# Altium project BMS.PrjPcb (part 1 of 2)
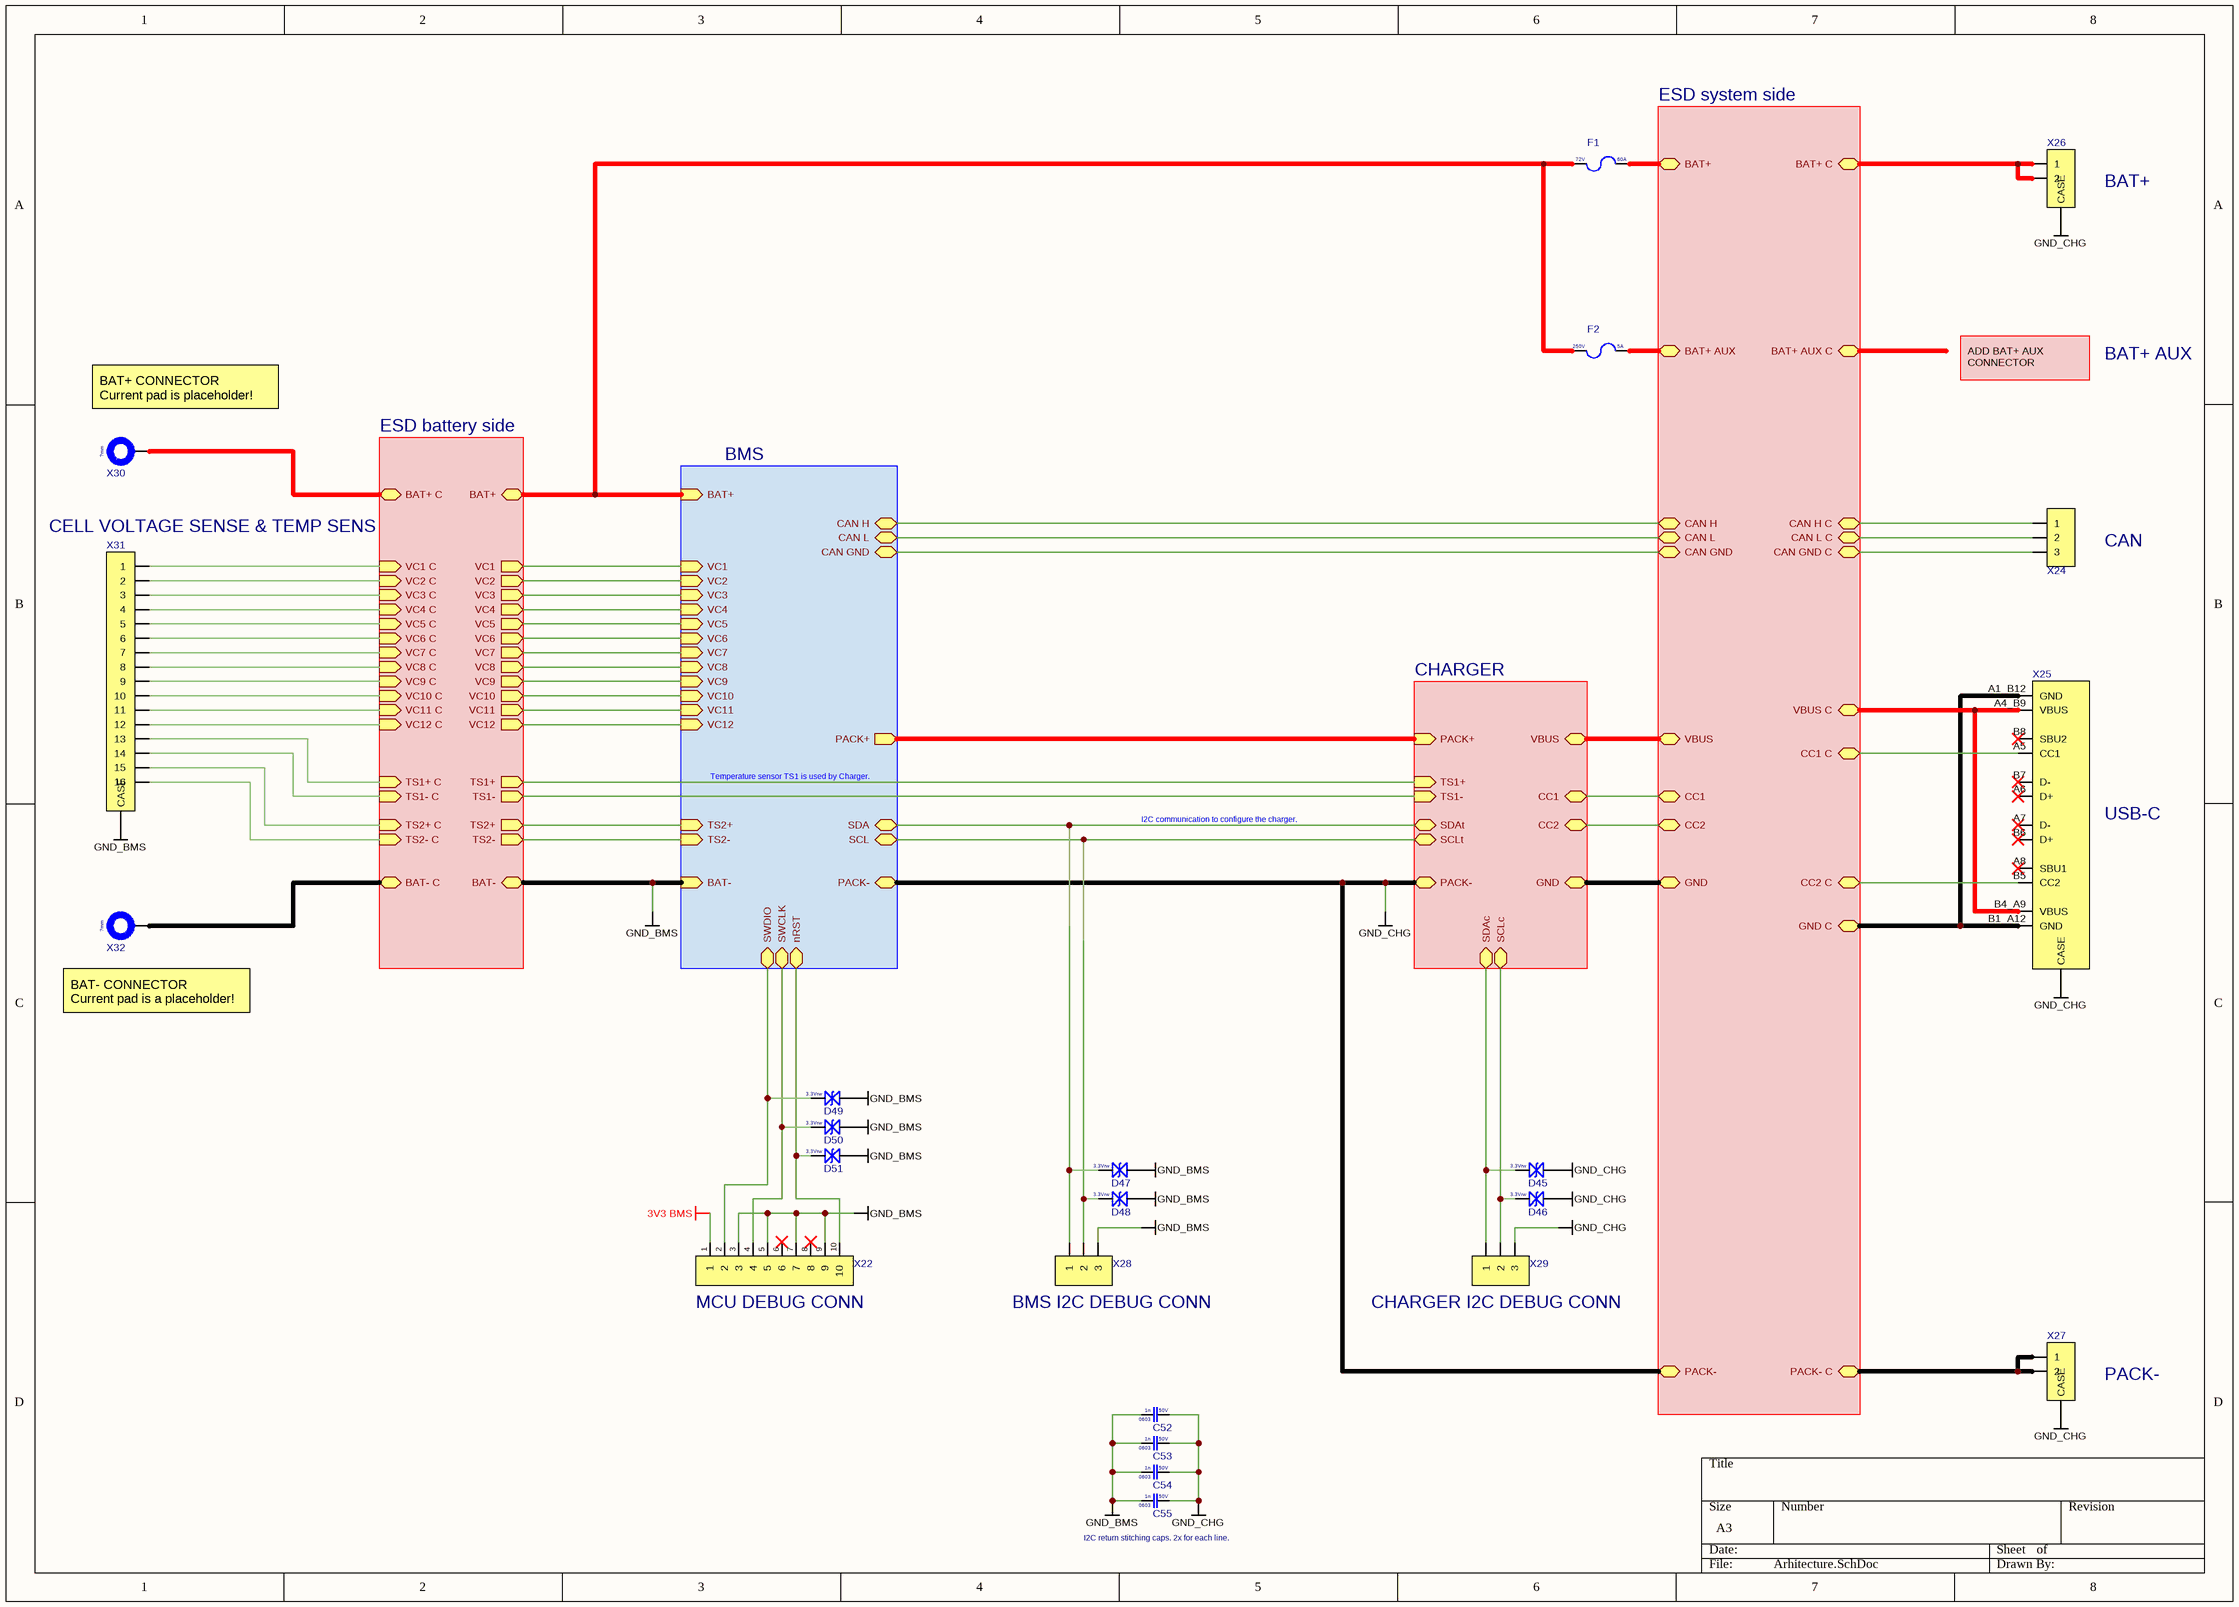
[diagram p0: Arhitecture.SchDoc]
15 sheets, 356 parts. Net scope: hierarchical (ports join the sheet entries above them; power ports are global).
Board file: PCB.PcbDoc
Sheets:
  Arhitecture.SchDoc
    BMS = BMS.SchDoc
      BQ76952 BMS = BQ76952 BMS.SchDoc
      BQ34Z100 FUEL GAUGE = BQ34Z100 FUEL GAUGE.SchDoc
      MCU = MCU.SchDoc
      BAT+ to 5V1 STEP-DOWN = BAT+ to 5V1 STEP-DOWN.SchDoc
      5V to 3V3 LDO = 5V to 3V3 LDO.SchDoc
    CHARGER = CHARGER.SchDoc
      USB PROTECTION = USB protection.SchDoc
      USB PD = USB PD.SchDoc
      POWER PATH SWITCH = Power path switch.SchDoc
      CHARGER BQ25756 = Charger BQ25756.SchDoc
      POWER DISTRIBUTION = Power distribution.SchDoc
    ESD system side = ESD system side.SchDoc
    ESD battery side = ESD battery side.SchDoc

## Sheet Arhitecture.SchDoc
size A3; SheetNumber: 1; SheetTotal: 15

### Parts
C52  Voltage Rating: 50V  Case Code (Imperial): 0603  Capacitance: 1n  [CAP 0603]  (hidden comment: CL10B102KB8NNNC)
C53  Voltage Rating: 50V  Case Code (Imperial): 0603  Capacitance: 1n  [CAP 0603]  (hidden comment: CL10B102KB8NNNC)
C54  Voltage Rating: 50V  Case Code (Imperial): 0603  Capacitance: 1n  [CAP 0603]  (hidden comment: CL10B102KB8NNNC)
C55  Voltage Rating: 50V  Case Code (Imperial): 0603  Capacitance: 1n  [CAP 0603]  (hidden comment: CL10B102KB8NNNC)
D45  V_RWM: 3.3Vrw  [SOD-523]  (hidden comment: H3V3LD5B)
D46  V_RWM: 3.3Vrw  [SOD-523]  (hidden comment: H3V3LD5B)
D47  V_RWM: 3.3Vrw  [SOD-523]  (hidden comment: H3V3LD5B)
D48  V_RWM: 3.3Vrw  [SOD-523]  (hidden comment: H3V3LD5B)
D49  V_RWM: 3.3Vrw  [SOD-523]  (hidden comment: H3V3LD5B)
D50  V_RWM: 3.3Vrw  [SOD-523]  (hidden comment: H3V3LD5B)
D51  V_RWM: 3.3Vrw  [SOD-523]  (hidden comment: H3V3LD5B)
F1  Voltage: 72V  Hold Current: 60A  [TB60]  (hidden comment: TB60)
F2  Voltage: 250V  Hold Current: 5A  [JFC2410-1500TS]  (hidden comment: JFC2410-1500TS)
X22  HX IDC127-2-05-S-4.9  [JTAG Cortex connector]  (value not drawn)
X24  S3B-XH-A-1(LF)(SN)  [S3B-XH-A-1(LF)(SN)]  (value not drawn)
X25  USB-TYPE-C-018  [TYPE-C 16PIN 2MD]  (value not drawn)
X26  XT30PW-M30.G.Y  [XT30PW-M30.G.Y]  (value not drawn)
X27  XT30PW-M30.G.Y  [XT30PW-M30.G.Y]  (value not drawn)
X28  2.54-1*3PPin  [Pin header 1x3 2.54mmP THT Vertical]  (value not drawn)
X29  2.54-1*3PPin  [Pin header 1x3 2.54mmP THT Vertical]  (value not drawn)
X30  Hole Diameter: ?mm  [SolderPad THT 1.9mm AWG14]  (hidden comment: Solder Pad THT)  (no BOM)
X31  FPC-1.0FX-16PWCR-H20  [FPC-1.0FX-16PWCR-H20]  (value not drawn)
X32  Hole Diameter: ?mm  [SolderPad THT 1.9mm AWG14]  (hidden comment: Solder Pad THT)  (no BOM)

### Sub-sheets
BMS = BMS.SchDoc: BAT+ (in), BAT- (in), VC1 (in), VC2 (in), VC3 (in), VC4 (in), VC5 (in), VC6 (in), VC7 (in), VC8 (in), VC9 (in), VC10 (in), VC11 (in), VC12 (in), PACK+ (out), PACK- (bidir), SCL (bidir), SDA (bidir), CAN H (bidir), CAN L (bidir), TS2+ (in), TS2- (in), SWDIO (bidir), SWCLK (bidir), nRST (bidir), CAN GND (bidir)
CHARGER = CHARGER.SchDoc: PACK+ (in), PACK- (bidir), SDAt (bidir), SCLt (bidir), TS1+ (in), TS1- (in), SDAc (bidir), SCLc (bidir), CC1 (bidir), CC2 (bidir), GND (bidir), VBUS (bidir)
ESD battery side = ESD battery side.schDoc: VC1 C (in), VC2 C (in), VC3 C (in), VC4 C (in), VC5 C (in), VC6 C (in), VC7 C (in), VC8 C (in), VC9 C (in), VC10 C (in), VC11 C (in), VC12 C (in), TS1+ C (in), TS1- C (in), TS2+ C (in), TS2- C (in), VC1 (out), VC2 (out), VC3 (out), VC4 (out), VC5 (out), VC6 (out), VC7 (out), VC8 (out), VC9 (out), VC10 (out), VC11 (out), VC12 (out), TS1+ (out), TS1- (out), TS2+ (out), TS2- (out), BAT+ C (bidir), BAT- C (bidir), BAT- (bidir), BAT+ (bidir)
ESD system side = ESD system side.SchDoc: CAN H (bidir), CAN L (bidir), CAN GND (bidir), CAN H C (bidir), CAN L C (bidir), CAN GND C (bidir), VBUS C (bidir), GND C (bidir), CC1 C (bidir), CC2 C (bidir), VBUS (bidir), CC1 (bidir), CC2 (bidir), GND (bidir), BAT+ C (bidir), BAT+ (bidir), PACK- C (bidir), PACK- (bidir), BAT+ AUX (bidir), BAT+ AUX C (bidir)

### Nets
3V3 BMS: X22.1  [project net VDD]
GND CAN: X24.3 ; sheet BMS/CAN GND, sheet ESD system side/CAN GND, sheet ESD system side/CAN GND C
GND_BMS: C52.1 C53.1 C54.1 C55.1 D47.A D48.A D49.A D50.A D51.A X22.3 X22.5 X22.7 X22.9 X28.3 X31.16 X31.CASE X32.1 ; sheet BMS/BAT-, sheet BMS/TS2-, sheet ESD battery side/TS2- C, sheet ESD battery side/TS2-, sheet ESD battery side/BAT- C, sheet ESD battery side/BAT-
GND_CHG: C52.2 C53.2 C54.2 C55.2 D45.A D46.A X25.A1_B12(GND) X25.B1_A12(GND) X25.CASE X26.CASE X27.1 X27.2 X27.CASE X29.3 ; sheet BMS/PACK-, sheet CHARGER/PACK-, sheet CHARGER/GND, sheet ESD system side/GND C, sheet ESD system side/GND, sheet ESD system side/PACK- C, sheet ESD system side/PACK-
BAT+: F1.1 F2.1 X30.1 ; sheet BMS/BAT+, sheet ESD battery side/BAT+ C, sheet ESD battery side/BAT+
C_CC1: X25.A5(CC1) ; sheet CHARGER/CC1, sheet ESD system side/CC1 C, sheet ESD system side/CC1
C_CC2: X25.B5(CC2) ; sheet CHARGER/CC2, sheet ESD system side/CC2 C, sheet ESD system side/CC2
CAN H: X24.1 ; sheet BMS/CAN H, sheet ESD system side/CAN H, sheet ESD system side/CAN H C
CAN L: X24.2 ; sheet BMS/CAN L, sheet ESD system side/CAN L, sheet ESD system side/CAN L C
nRST: D51.K X22.10 ; sheet BMS/nRST
PACK+: sheet BMS/PACK+, sheet CHARGER/PACK+
SCL: D46.K X29.2 ; sheet CHARGER/SCLc
SCLt: D48.K X28.2 ; sheet BMS/SCL, sheet CHARGER/SCLt
SDA: D45.K X29.1 ; sheet CHARGER/SDAc
SDAt: D47.K X28.1 ; sheet BMS/SDA, sheet CHARGER/SDAt
TS: X31.13 ; sheet CHARGER/TS1+, sheet ESD battery side/TS1+ C, sheet ESD battery side/TS1+
VBUS: X25.A4_B9(VBUS) X25.B4_A9(VBUS) ; sheet CHARGER/VBUS, sheet ESD system side/VBUS C, sheet ESD system side/VBUS
NetC75_2: F2.2 ; sheet ESD system side/BAT+ AUX, sheet ESD system side/BAT+ AUX C
NetC83_2: X31.15 ; sheet BMS/TS2+, sheet ESD battery side/TS2+ C, sheet ESD battery side/TS2+
NetC107_2: F1.2 X26.1 X26.2 ; sheet ESD system side/BAT+ C, sheet ESD system side/BAT+
NetD40_A: X31.14 ; sheet CHARGER/TS1-, sheet ESD battery side/TS1- C, sheet ESD battery side/TS1-
NetD49_K: D49.K X22.2 ; sheet BMS/SWDIO
NetD50_K: D50.K X22.4 ; sheet BMS/SWCLK
NetR65_1: X31.12 ; sheet BMS/VC12, sheet ESD battery side/VC12 C, sheet ESD battery side/VC12
NetR66_1: X31.11 ; sheet BMS/VC11, sheet ESD battery side/VC11 C, sheet ESD battery side/VC11
NetR67_1: X31.10 ; sheet BMS/VC10, sheet ESD battery side/VC10 C, sheet ESD battery side/VC10
NetR68_1: X31.9 ; sheet BMS/VC9, sheet ESD battery side/VC9 C, sheet ESD battery side/VC9
NetR69_1: X31.8 ; sheet BMS/VC8, sheet ESD battery side/VC8 C, sheet ESD battery side/VC8
NetR70_1: X31.7 ; sheet BMS/VC7, sheet ESD battery side/VC7 C, sheet ESD battery side/VC7
NetR71_1: X31.6 ; sheet BMS/VC6, sheet ESD battery side/VC6 C, sheet ESD battery side/VC6
NetR72_1: X31.5 ; sheet BMS/VC5, sheet ESD battery side/VC5 C, sheet ESD battery side/VC5
NetR73_1: X31.4 ; sheet BMS/VC4, sheet ESD battery side/VC4 C, sheet ESD battery side/VC4
NetR74_1: X31.3 ; sheet BMS/VC3, sheet ESD battery side/VC3 C, sheet ESD battery side/VC3
NetR75_1: X31.2 ; sheet BMS/VC2, sheet ESD battery side/VC2 C, sheet ESD battery side/VC2
NetR76_1: X31.1 ; sheet BMS/VC1, sheet ESD battery side/VC1 C, sheet ESD battery side/VC1

Not connected (* = marked no-connect by the designer): X22 6* 8*; X25 A6(D+)* A7(D-)* A8(SBU1)* B6(D+)* B7(D-)* B8(SBU2)*

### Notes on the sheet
- (near X26) BAT+
- (near X30) BAT+ CONNECTOR
  Current pad is placeholder!
- ADD BAT+ AUX CONNECTOR
- BAT+ AUX
- (near X31) CELL VOLTAGE SENSE & TEMP SENS
- CAN
- Temperature sensor TS1 is used by Charger.
- I2C communication to configure the charger.
- (near X25) USB-C
- (near X32) BAT- CONNECTOR
  Current pad is a placeholder!
- (near X22) MCU DEBUG CONN
- (near X28) BMS I2C DEBUG CONN
- (near X29) CHARGER I2C DEBUG CONN
- (near X27) PACK-
- (near C55) I2C return stitching caps. 2x for each line.

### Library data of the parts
C52-C55 = CL10B102KB8NNNC: Cap 1nF 50V 0603 X7R; Manufacturer: Samsung
D45-D51 = H3V3LD5B: ESD TVS 3.3Vrw 0.2uA 12.5pF; Manufacturer: hongjiacheng
F1 = TB60: Fuse SMD 60A 72V 10.3x3.2mm; Manufacturer: TLC Electronic
F2 = JFC2410-1500TS: Fuse SMD 250V 5A 2410; Manufacturer: JDT Fuse
X22 = HX IDC127-2-05-S-4.9: JTAG Cortex MCU Debug connector 2x5P 1.27mmP; Manufacturer: hanxia
X24 = S3B-XH-A-1(LF)(SN): JST XH 1x3 2.50mmP THT Right-angle
X25 = USB-TYPE-C-018: USB-C 16P Right-angle; Manufacturer: DEALON
X26 X27 = XT30PW-M30.G.Y: XT30 Male THT Right-angle; Manufacturer: Changzhou Amass Elec
X28 X29 = 2.54-1*3PPin: Pin header 1x3 2.54mmP THT Vertical; Manufacturer: BOOMELE
X31 = FPC-1.0FX-16PWCR-H20: FPC connector 16p 1.0mmP SMD Right-angle; Manufacturer: XUNPU

## Sheet BMS.SchDoc
size A3; SheetNumber: 8; SheetTotal: 15
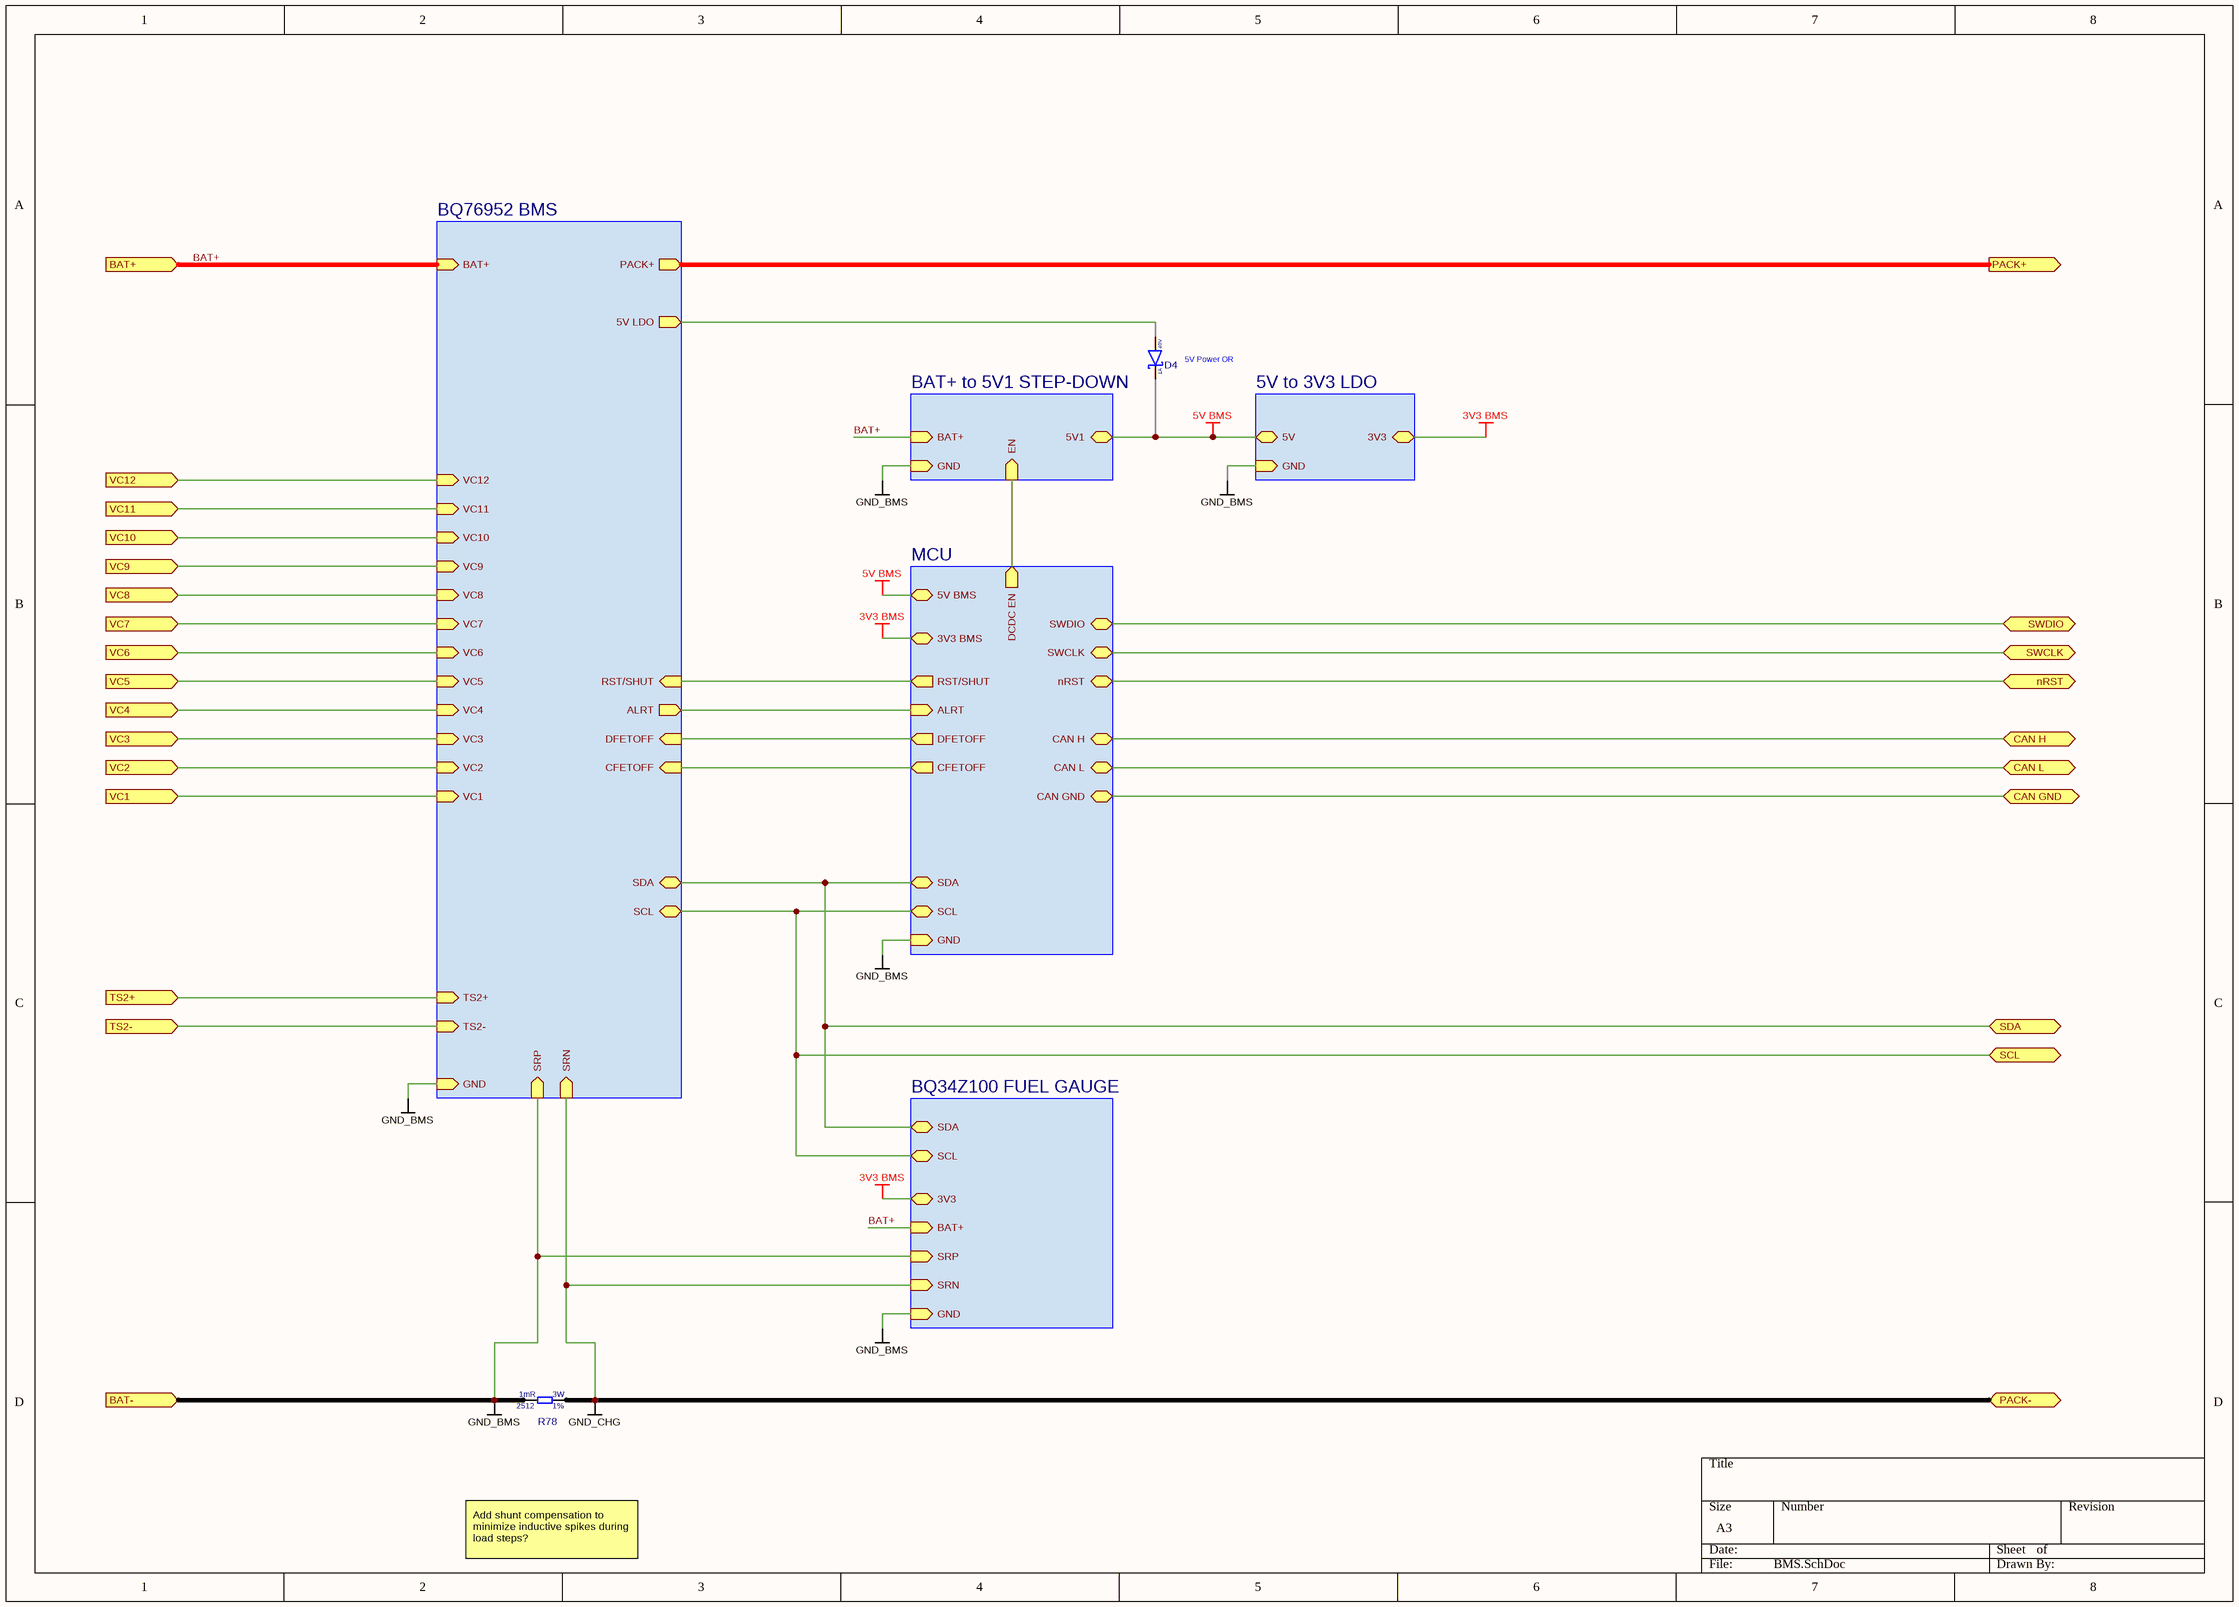
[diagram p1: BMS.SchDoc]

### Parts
D4  Forward Current: 1A  Reverse Voltage: 40V  [SOD-323]  (hidden comment: 1N5819WS)
R78  Resistance Tolerance: 1%  Resistance: 1mR  Power Rating: 3W  Case Code (Imperial): 2512  [2512 Shunt]  (hidden comment: HoYLR2512E-3W-1mR-1%)

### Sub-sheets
5V to 3V3 LDO = 5V to 3V3 LDO.SchDoc: 5V (bidir), 3V3 (bidir), GND (in)
BAT+ to 5V1 STEP-DOWN = BAT+ to 5V1 STEP-DOWN.SchDoc: 5V1 (bidir), BAT+ (in), EN (in), GND (in)
BQ34Z100 FUEL GAUGE = BQ34Z100 FUEL GAUGE.SchDoc: SRP (in), SRN (in), SDA (bidir), SCL (bidir), BAT+ (in), GND (in), 3V3 (bidir)
BQ76952 BMS = BQ76952 BMS.SchDoc: VC12 (in), VC11 (in), VC10 (in), VC9 (in), VC8 (in), VC7 (in), VC6 (in), VC5 (in), VC4 (in), VC3 (in), VC2 (in), VC1 (in), TS2+ (in), TS2- (in), BAT+ (in), PACK+ (out), 5V LDO (out), SRP (in), SRN (in), SDA (bidir), SCL (bidir), ALRT (out), DFETOFF (in), CFETOFF (in), RST/SHUT (in), GND (in)
MCU = MCU.SchDoc: DCDC EN (out), 5V BMS (bidir), 3V3 BMS (bidir), SDA (bidir), SCL (bidir), ALRT (in), DFETOFF (out), CFETOFF (out), RST/SHUT (out), CAN H (bidir), CAN L (bidir), GND (in), nRST (bidir), SWCLK (bidir), SWDIO (bidir), CAN GND (bidir)

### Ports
BAT+ (in, see Arhitecture[3B], BAT+ to 5V1 STEP-DOWN[3B], BQ34Z100 FUEL GAUGE[3A], BQ76952 BMS[1A], ESD battery side[5A]), BAT- (in, see Arhitecture[3C], ESD battery side[5C]), CAN GND (bidir, see Arhitecture[4B], ESD system side[3B], MCU[8B]), CAN H (bidir, see Arhitecture[4B], ESD system side[3B], MCU[8A]), CAN L (bidir, see Arhitecture[4B], ESD system side[3B], MCU[8B]), nRST (bidir, see Arhitecture[3C], MCU[8C]), PACK+ (out, see Arhitecture[4B], BQ76952 BMS[8A], Charger BQ25756[1A], CHARGER[1B], Power distribution[3A]), PACK- (bidir, see Arhitecture[4C], CHARGER[1C], ESD system side[3C]), SCL (bidir, see Arhitecture[4C], BQ34Z100 FUEL GAUGE[5B], BQ76952 BMS[7C], MCU[1B]), SDA (bidir, see Arhitecture[4C], BQ34Z100 FUEL GAUGE[5B], BQ76952 BMS[7C], MCU[1B]), SWCLK (bidir, see Arhitecture[3C], MCU[8C]), SWDIO (bidir, see Arhitecture[3C], MCU[8C]), TS2+ (in, see Arhitecture[3C], BQ76952 BMS[3C], ESD battery side[5C]), TS2- (in, see Arhitecture[3C], BQ76952 BMS[3C], ESD battery side[5C]), VC1 (in, see Arhitecture[3B], BQ76952 BMS[1C], ESD battery side[5B]), VC2 (in, see Arhitecture[3B], BQ76952 BMS[1C], ESD battery side[5B]), VC3 (in, see Arhitecture[3B], BQ76952 BMS[1C], ESD battery side[5B]), VC4 (in, see Arhitecture[3B], BQ76952 BMS[1C], ESD battery side[5B]), VC5 (in, see Arhitecture[3B], BQ76952 BMS[1C], ESD battery side[5B]), VC6 (in, see Arhitecture[3B], BQ76952 BMS[1C], ESD battery side[5B]), VC7 (in, see Arhitecture[3B], BQ76952 BMS[1C], ESD battery side[5B]), VC8 (in, see Arhitecture[3B], BQ76952 BMS[1B], ESD battery side[5B]), VC9 (in, see Arhitecture[3B], BQ76952 BMS[1B], ESD battery side[5B]), VC10 (in, see Arhitecture[3B], BQ76952 BMS[1B], ESD battery side[5B]), VC11 (in, see Arhitecture[3B], BQ76952 BMS[1B], ESD battery side[5B]), VC12 (in, see Arhitecture[3B], BQ76952 BMS[1B], ESD battery side[5B])

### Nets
3V3 BMS: sheet BQ34Z100 FUEL GAUGE/3V3, sheet MCU/3V3 BMS, sheet 5V to 3V3 LDO/3V3  [project net VDD]
5V BMS: D4.K ; sheet MCU/5V BMS, sheet BAT+ to 5V1 STEP-DOWN/5V1, sheet 5V to 3V3 LDO/5V
GND CAN: port CAN GND, sheet MCU/CAN GND
GND_BMS: R78.1 ; port BAT-, port TS2-, sheet BQ76952 BMS/TS2-, sheet BQ76952 BMS/SRP, sheet BQ76952 BMS/GND, sheet BQ34Z100 FUEL GAUGE/SRP, sheet BQ34Z100 FUEL GAUGE/GND, sheet MCU/GND, sheet BAT+ to 5V1 STEP-DOWN/GND, sheet 5V to 3V3 LDO/GND
GND_CHG: R78.2 ; port PACK-, sheet BQ76952 BMS/SRN, sheet BQ34Z100 FUEL GAUGE/SRN
BAT+: port BAT+, sheet BQ76952 BMS/BAT+, sheet BQ34Z100 FUEL GAUGE/BAT+, sheet BAT+ to 5V1 STEP-DOWN/BAT+
CAN H: port CAN H, sheet MCU/CAN H
CAN L: port CAN L, sheet MCU/CAN L
nRST: port nRST, sheet MCU/nRST
PACK+: port PACK+, sheet BQ76952 BMS/PACK+
REG1: D4.A ; sheet BQ76952 BMS/5V LDO
SCLt: port SCL, sheet BQ76952 BMS/SCL, sheet BQ34Z100 FUEL GAUGE/SCL, sheet MCU/SCL
SDAt: port SDA, sheet BQ76952 BMS/SDA, sheet BQ34Z100 FUEL GAUGE/SDA, sheet MCU/SDA
NetC83_2: port TS2+, sheet BQ76952 BMS/TS2+
NetD49_K: port SWDIO, sheet MCU/SWDIO
NetD50_K: port SWCLK, sheet MCU/SWCLK
NetIC9_29: sheet BQ76952 BMS/CFETOFF, sheet MCU/CFETOFF
NetIC9_30: sheet BQ76952 BMS/DFETOFF, sheet MCU/DFETOFF
NetIC10_16: sheet BQ76952 BMS/ALRT, sheet MCU/ALRT
NetIC10_17: sheet BQ76952 BMS/RST/SHUT, sheet MCU/RST/SHUT
NetIC13_3: sheet MCU/DCDC EN, sheet BAT+ to 5V1 STEP-DOWN/EN
NetR65_1: port VC12, sheet BQ76952 BMS/VC12
NetR66_1: port VC11, sheet BQ76952 BMS/VC11
NetR67_1: port VC10, sheet BQ76952 BMS/VC10
NetR68_1: port VC9, sheet BQ76952 BMS/VC9
NetR69_1: port VC8, sheet BQ76952 BMS/VC8
NetR70_1: port VC7, sheet BQ76952 BMS/VC7
NetR71_1: port VC6, sheet BQ76952 BMS/VC6
NetR72_1: port VC5, sheet BQ76952 BMS/VC5
NetR73_1: port VC4, sheet BQ76952 BMS/VC4
NetR74_1: port VC3, sheet BQ76952 BMS/VC3
NetR75_1: port VC2, sheet BQ76952 BMS/VC2
NetR76_1: port VC1, sheet BQ76952 BMS/VC1

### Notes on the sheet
- (near D4) 5V Power OR
- Add shunt compensation to minimize inductive spikes during load steps?

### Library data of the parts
D4 = 1N5819WS: Schottky 40V 1A 600mVf SOD-323; Manufacturer: Guangdong Hottech
R78 = HoYLR2512E-3W-1mR-1%: RES 1mR 2512 3W 1%; Manufacturer: Miliohm

## Sheet BQ76952 BMS.SchDoc
size A3; SheetNumber: 9; SheetTotal: 15
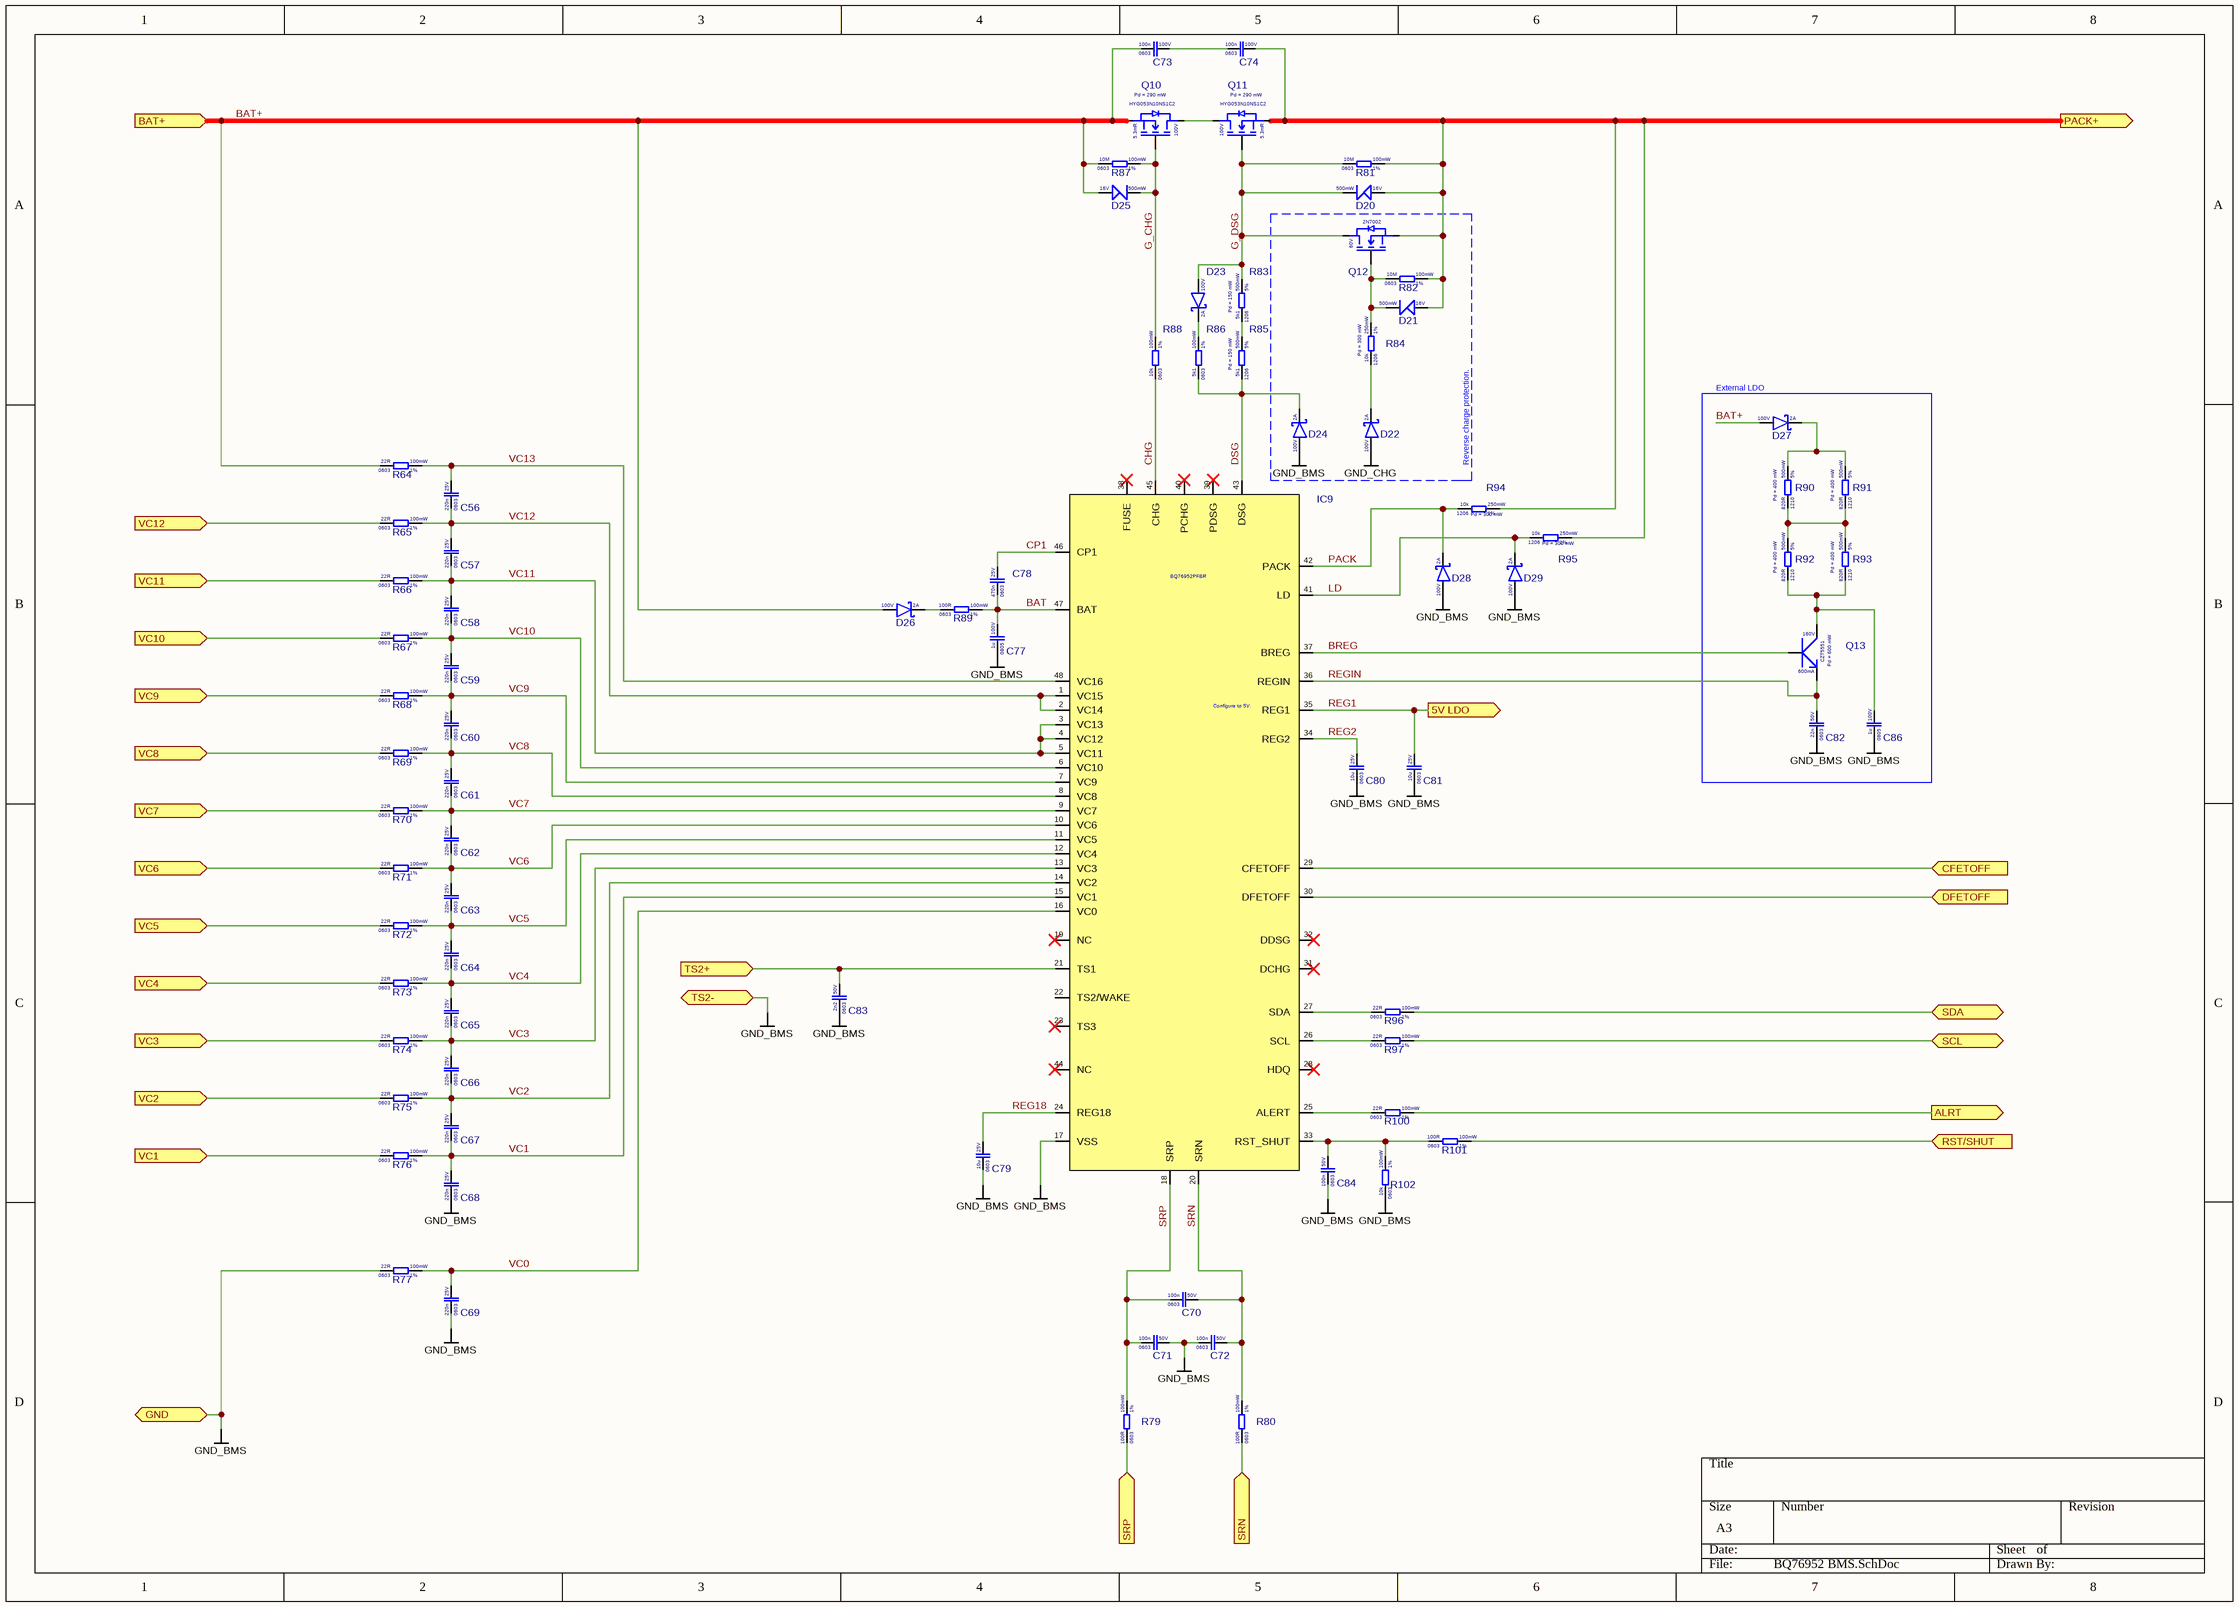
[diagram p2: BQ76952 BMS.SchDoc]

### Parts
C56  Voltage Rating: 25V  Case Code (Imperial): 0603  Capacitance: 220n  [CAP 0603]  (hidden comment: CL10B224KA8NNNC)
C57  Voltage Rating: 25V  Case Code (Imperial): 0603  Capacitance: 220n  [CAP 0603]  (hidden comment: CL10B224KA8NNNC)
C58  Voltage Rating: 25V  Case Code (Imperial): 0603  Capacitance: 220n  [CAP 0603]  (hidden comment: CL10B224KA8NNNC)
C59  Voltage Rating: 25V  Case Code (Imperial): 0603  Capacitance: 220n  [CAP 0603]  (hidden comment: CL10B224KA8NNNC)
C60  Voltage Rating: 25V  Case Code (Imperial): 0603  Capacitance: 220n  [CAP 0603]  (hidden comment: CL10B224KA8NNNC)
C61  Voltage Rating: 25V  Case Code (Imperial): 0603  Capacitance: 220n  [CAP 0603]  (hidden comment: CL10B224KA8NNNC)
C62  Voltage Rating: 25V  Case Code (Imperial): 0603  Capacitance: 220n  [CAP 0603]  (hidden comment: CL10B224KA8NNNC)
C63  Voltage Rating: 25V  Case Code (Imperial): 0603  Capacitance: 220n  [CAP 0603]  (hidden comment: CL10B224KA8NNNC)
C64  Voltage Rating: 25V  Case Code (Imperial): 0603  Capacitance: 220n  [CAP 0603]  (hidden comment: CL10B224KA8NNNC)
C65  Voltage Rating: 25V  Case Code (Imperial): 0603  Capacitance: 220n  [CAP 0603]  (hidden comment: CL10B224KA8NNNC)
C66  Voltage Rating: 25V  Case Code (Imperial): 0603  Capacitance: 220n  [CAP 0603]  (hidden comment: CL10B224KA8NNNC)
C67  Voltage Rating: 25V  Case Code (Imperial): 0603  Capacitance: 220n  [CAP 0603]  (hidden comment: CL10B224KA8NNNC)
C68  Voltage Rating: 25V  Case Code (Imperial): 0603  Capacitance: 220n  [CAP 0603]  (hidden comment: CL10B224KA8NNNC)
C69  Voltage Rating: 25V  Case Code (Imperial): 0603  Capacitance: 220n  [CAP 0603]  (hidden comment: CL10B224KA8NNNC)
C70  Voltage Rating: 50V  Case Code (Imperial): 0603  Capacitance: 100n  [CAP 0603]  (hidden comment: CC0603KRX7R9BB104)
C71  Voltage Rating: 50V  Case Code (Imperial): 0603  Capacitance: 100n  [CAP 0603]  (hidden comment: CC0603KRX7R9BB104)
C72  Voltage Rating: 50V  Case Code (Imperial): 0603  Capacitance: 100n  [CAP 0603]  (hidden comment: CC0603KRX7R9BB104)
C73  Voltage Rating: 100V  Case Code (Imperial): 0603  Capacitance: 100n  [CAP 0603]  (hidden comment: CC0603KRX7R0BB104)
C74  Voltage Rating: 100V  Case Code (Imperial): 0603  Capacitance: 100n  [CAP 0603]  (hidden comment: CC0603KRX7R0BB104)
C77  Voltage Rating: 100V  Case Code (Imperial): 0805  Capacitance: 1u  [Cap_0805]  (hidden comment: CC0805KKX7R0BB105)
C78  Voltage Rating: 25V  Case Code (Imperial): 0603  Capacitance: 470n  [CAP 0603]  (hidden comment: CL10B474KA8NNNC)
C79  Voltage Rating: 25V  Case Code (Imperial): 0603  Capacitance: 10u  [CAP 0603]  (hidden comment: CL10A106MA8NRNC)
C80  Voltage Rating: 25V  Case Code (Imperial): 0603  Capacitance: 10u  [CAP 0603]  (hidden comment: CL10A106MA8NRNC)
C81  Voltage Rating: 25V  Case Code (Imperial): 0603  Capacitance: 10u  [CAP 0603]  (hidden comment: CL10A106MA8NRNC)
C82  Voltage Rating: 50V  Case Code (Imperial): 0603  Capacitance: 22n  [CAP 0603]  (hidden comment: CL10B223KB8NNNC)
C83  Voltage Rating: 50V  Case Code (Imperial): 0603  Capacitance: 2n2  [CAP 0603]  (hidden comment: 0603B222K500NT)
C84  Voltage Rating: 50V  Case Code (Imperial): 0603  Capacitance: 100n  [CAP 0603]  (hidden comment: CC0603KRX7R9BB104)
C86  Voltage Rating: 100V  Case Code (Imperial): 0805  Capacitance: 1u  [Cap_0805]  (hidden comment: CC0805KKX7R0BB105)
D20  Power Rating: 500mW  Reverse Voltage: 16V  [SOD-123]  (hidden comment: BZT52C16)
D21  Power Rating: 500mW  Reverse Voltage: 16V  [SOD-123]  (hidden comment: BZT52C16)
D22  Forward Current: 2A  Reverse Voltage: 100V  [SMAF]  (hidden comment: SS210F)
D23  Forward Current: 2A  Reverse Voltage: 100V  [SMAF]  (hidden comment: SS210F)
D24  Forward Current: 2A  Reverse Voltage: 100V  [SMAF]  (hidden comment: SS210F)
D25  Power Rating: 500mW  Reverse Voltage: 16V  [SOD-123]  (hidden comment: BZT52C16)
D26  Forward Current: 2A  Reverse Voltage: 100V  [SMAF]  (hidden comment: SS210F)
D27  Forward Current: 2A  Reverse Voltage: 100V  [SMAF]  (hidden comment: SS210F)
D28  Forward Current: 2A  Reverse Voltage: 100V  [SMAF]  (hidden comment: SS210F)
D29  Forward Current: 2A  Reverse Voltage: 100V  [SMAF]  (hidden comment: SS210F)
IC9  BQ76952PFBR  [TQFP-48 PFB]
Q10  Pd = 290 mW  Rds: 5.3mR  Voltage: 100V  [PDFN5*6-8L]
Q11  Pd = 290 mW  Rds: 5.3mR  Voltage: 100V  [PDFN5*6-8L]
Q12  Voltage: 60V  [SOT-23 GSD]  (hidden comment: 2N7002)
Q13  Pd = 600 mW  Current: 600mA  Voltage: 160V  [SOT-223 NPN]
R64  Resistance Tolerance: 1%  Resistance: 22R  Power Rating: 100mW  Case Code (Imperial): 0603  [RES_0603]  (hidden comment: 0603WAF220JT5E)
R65  Resistance Tolerance: 1%  Resistance: 22R  Power Rating: 100mW  Case Code (Imperial): 0603  [RES_0603]  (hidden comment: 0603WAF220JT5E)
R66  Resistance Tolerance: 1%  Resistance: 22R  Power Rating: 100mW  Case Code (Imperial): 0603  [RES_0603]  (hidden comment: 0603WAF220JT5E)
R67  Resistance Tolerance: 1%  Resistance: 22R  Power Rating: 100mW  Case Code (Imperial): 0603  [RES_0603]  (hidden comment: 0603WAF220JT5E)
R68  Resistance Tolerance: 1%  Resistance: 22R  Power Rating: 100mW  Case Code (Imperial): 0603  [RES_0603]  (hidden comment: 0603WAF220JT5E)
R69  Resistance Tolerance: 1%  Resistance: 22R  Power Rating: 100mW  Case Code (Imperial): 0603  [RES_0603]  (hidden comment: 0603WAF220JT5E)
R70  Resistance Tolerance: 1%  Resistance: 22R  Power Rating: 100mW  Case Code (Imperial): 0603  [RES_0603]  (hidden comment: 0603WAF220JT5E)
R71  Resistance Tolerance: 1%  Resistance: 22R  Power Rating: 100mW  Case Code (Imperial): 0603  [RES_0603]  (hidden comment: 0603WAF220JT5E)
R72  Resistance Tolerance: 1%  Resistance: 22R  Power Rating: 100mW  Case Code (Imperial): 0603  [RES_0603]  (hidden comment: 0603WAF220JT5E)
R73  Resistance Tolerance: 1%  Resistance: 22R  Power Rating: 100mW  Case Code (Imperial): 0603  [RES_0603]  (hidden comment: 0603WAF220JT5E)
R74  Resistance Tolerance: 1%  Resistance: 22R  Power Rating: 100mW  Case Code (Imperial): 0603  [RES_0603]  (hidden comment: 0603WAF220JT5E)
R75  Resistance Tolerance: 1%  Resistance: 22R  Power Rating: 100mW  Case Code (Imperial): 0603  [RES_0603]  (hidden comment: 0603WAF220JT5E)
R76  Resistance Tolerance: 1%  Resistance: 22R  Power Rating: 100mW  Case Code (Imperial): 0603  [RES_0603]  (hidden comment: 0603WAF220JT5E)
R77  Resistance Tolerance: 1%  Resistance: 22R  Power Rating: 100mW  Case Code (Imperial): 0603  [RES_0603]  (hidden comment: 0603WAF220JT5E)
R79  Resistance Tolerance: 1%  Resistance: 100R  Power Rating: 100mW  Case Code (Imperial): 0603  [RES_0603]  (hidden comment: 0603WAF1000T5E)
R80  Resistance Tolerance: 1%  Resistance: 100R  Power Rating: 100mW  Case Code (Imperial): 0603  [RES_0603]  (hidden comment: 0603WAF1000T5E)
R81  Resistance Tolerance: 1%  Resistance: 10M  Power Rating: 100mW  Case Code (Imperial): 0603  [RES_0603]  (hidden comment: 0603WAF1005T5E)
R82  Resistance Tolerance: 1%  Resistance: 10M  Power Rating: 100mW  Case Code (Imperial): 0603  [RES_0603]  (hidden comment: 0603WAF1005T5E)
R83  Pd = 150 mW  Resistance Tolerance: 5%  Resistance: 5k1  Power Rating: 500mW  Case Code (Imperial): 1206  [RES_1206]
R84  Pd = 300 mW  Resistance Tolerance: 1%  Resistance: 10k  Power Rating: 250mW  Case Code (Imperial): 1206  [RES_1206]
R85  Pd = 150 mW  Resistance Tolerance: 5%  Resistance: 5k1  Power Rating: 500mW  Case Code (Imperial): 1206  [RES_1206]
R86  Resistance Tolerance: 1%  Resistance: 5k1  Power Rating: 100mW  Case Code (Imperial): 0603  [RES_0603]  (hidden comment: 0603WAF5101T5E)
R87  Resistance Tolerance: 1%  Resistance: 10M  Power Rating: 100mW  Case Code (Imperial): 0603  [RES_0603]  (hidden comment: 0603WAF1005T5E)
R88  Resistance Tolerance: 1%  Resistance: 10k  Power Rating: 100mW  Case Code (Imperial): 0603  [RES_0603]  (hidden comment: 0603WAF1002T5E)
R89  Resistance Tolerance: 1%  Resistance: 100R  Power Rating: 100mW  Case Code (Imperial): 0603  [RES_0603]  (hidden comment: 0603WAF1000T5E)
R90  Pd = 400 mW  Resistance Tolerance: 5%  Resistance: 820R  Power Rating: 500mW  Case Code (Imperial): 1210  [RES_1210]
R91  Pd = 400 mW  Resistance Tolerance: 5%  Resistance: 820R  Power Rating: 500mW  Case Code (Imperial): 1210  [RES_1210]
R92  Pd = 400 mW  Resistance Tolerance: 5%  Resistance: 820R  Power Rating: 500mW  Case Code (Imperial): 1210  [RES_1210]
R93  Pd = 400 mW  Resistance Tolerance: 5%  Resistance: 820R  Power Rating: 500mW  Case Code (Imperial): 1210  [RES_1210]
R94  Pd = 300 mW  Resistance Tolerance: 1%  Resistance: 10k  Power Rating: 250mW  Case Code (Imperial): 1206  [RES_1206]
R95  Pd = 300 mW  Resistance Tolerance: 1%  Resistance: 10k  Power Rating: 250mW  Case Code (Imperial): 1206  [RES_1206]
R96  Resistance Tolerance: 1%  Resistance: 22R  Power Rating: 100mW  Case Code (Imperial): 0603  [RES_0603]  (hidden comment: 0603WAF220JT5E)
R97  Resistance Tolerance: 1%  Resistance: 22R  Power Rating: 100mW  Case Code (Imperial): 0603  [RES_0603]  (hidden comment: 0603WAF220JT5E)
R100  Resistance Tolerance: 1%  Resistance: 22R  Power Rating: 100mW  Case Code (Imperial): 0603  [RES_0603]  (hidden comment: 0603WAF220JT5E)
R101  Resistance Tolerance: 1%  Resistance: 100R  Power Rating: 100mW  Case Code (Imperial): 0603  [RES_0603]  (hidden comment: 0603WAF1000T5E)
R102  Resistance Tolerance: 1%  Resistance: 10k  Power Rating: 100mW  Case Code (Imperial): 0603  [RES_0603]  (hidden comment: 0603WAF1002T5E)

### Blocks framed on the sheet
External LDO: C82 C86 D27 Q13 R90-R93

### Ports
5V LDO (out, see BMS[3A]), ALRT (out, see BMS[3B], MCU[1C]), BAT+ (in, see BMS[2A], BAT+ to 5V1 STEP-DOWN[3B], BMS[1A], BQ34Z100 FUEL GAUGE[3A], ESD battery side[5A]), CFETOFF (in, see BMS[3B], MCU[1C]), DFETOFF (in, see BMS[3B], MCU[1C]), GND (bidir, see BMS[2C], 5V to 3V3 LDO[3B], BAT+ to 5V1 STEP-DOWN[3C], BQ34Z100 FUEL GAUGE[3C], MCU[1C]), PACK+ (out, see BMS[3A], BMS[8A], Charger BQ25756[1A], CHARGER[1B], Power distribution[3A]), RST/SHUT (in, see BMS[3B], MCU[1C]), SCL (bidir, see BMS[3C], BMS[8C], BQ34Z100 FUEL GAUGE[5B], MCU[1B]), SDA (bidir, see BMS[3C], BMS[8C], BQ34Z100 FUEL GAUGE[5B], MCU[1B]), SRN (in, see BMS[3C], BQ34Z100 FUEL GAUGE[4C]), SRP (in, see BMS[2C], BQ34Z100 FUEL GAUGE[4C]), TS2+ (in, see BMS[2C], BMS[1C], ESD battery side[5C]), TS2- (bidir, see BMS[2C], BMS[1C], ESD battery side[5C]), VC1 (in, see BMS[2B], BMS[1B], ESD battery side[5B]), VC2 (in, see BMS[2B], BMS[1B], ESD battery side[5B]), VC3 (in, see BMS[2B], BMS[1B], ESD battery side[5B]), VC4 (in, see BMS[2B], BMS[1B], ESD battery side[5B]), VC5 (in, see BMS[2B], BMS[1B], ESD battery side[5B]), VC6 (in, see BMS[2B], BMS[1B], ESD battery side[5B]), VC7 (in, see BMS[2B], BMS[1B], ESD battery side[5B]), VC8 (in, see BMS[2B], BMS[1B], ESD battery side[5B]), VC9 (in, see BMS[2B], BMS[1B], ESD battery side[5B]), VC10 (in, see BMS[2B], BMS[1B], ESD battery side[5B]), VC11 (in, see BMS[2B], BMS[1B], ESD battery side[5B]), VC12 (in, see BMS[2B], BMS[1B], ESD battery side[5B])

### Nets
GND_BMS: C68.1 C69.1 C71.2 C72.1 C77.1 C79.1 C80.1 C81.1 C82.1 C83.1 C84.1 C86.1 D24.A D28.A D29.A IC9.17(VSS) R77.1 R79.1 R102.1 ; port TS2-, port SRP, port GND
GND_CHG: D22.A R80.1 ; port SRN
BAT: C77.2 C78.1 IC9.47(BAT) R89.2
BAT+: C73.1 D25.A D26.A D27.A Q10.S R64.1 R87.1 ; port BAT+
BREG: IC9.37(BREG) Q13.B
CHG: IC9.45(CHG) R88.1
CP1: C78.2 IC9.46(CP1)
DSG: D24.K IC9.43(DSG) R85.1 R86.1
G_CHG: D25.K Q10.G R87.2 R88.2
G_DSG: D20.K D23.A Q11.G Q12.D R81.1 R83.2
LD: D29.K IC9.41(LD) R95.1
PACK: D28.K IC9.42(PACK) R94.1
PACK+: C74.2 D20.A D21.A Q11.S Q12.S R81.2 R82.2 R94.2 R95.2 ; port PACK+
REG1: C81.2 IC9.35(REG1) ; port 5V LDO
REG2: C80.2 IC9.34(REG2)
REG18: C79.2 IC9.24(REG18)
REGIN: C82.2 IC9.36(REGIN) Q13.E
SCLt: R97.2 ; port SCL
SDAt: R96.2 ; port SDA
SRN: C70.2 C72.2 IC9.20(SRN) R80.2
SRP: C70.1 C71.1 IC9.18(SRP) R79.2
VC0: C69.2 IC9.16(VC0) R77.2
VC1: C67.1 C68.2 IC9.15(VC1) R76.2
VC2: C66.1 C67.2 IC9.14(VC2) R75.2
VC3: C65.1 C66.2 IC9.13(VC3) R74.2
VC4: C64.1 C65.2 IC9.12(VC4) R73.2
VC5: C63.1 C64.2 IC9.11(VC5) R72.2
VC6: C62.1 C63.2 IC9.10(VC6) R71.2
VC7: C61.1 C62.2 IC9.9(VC7) R70.2
VC8: C60.1 C61.2 IC9.8(VC8) R69.2
VC9: C59.1 C60.2 IC9.7(VC9) R68.2
VC10: C58.1 C59.2 IC9.6(VC10) R67.2
VC11: C57.1 C58.2 IC9.3(VC13) IC9.4(VC12) IC9.5(VC11) R66.2
VC12: C56.1 C57.2 IC9.1(VC15) IC9.2(VC14) R65.2
VC13: C56.2 IC9.48(VC16) R64.2
NetC73_2: C73.2 C74.1
NetC83_2: C83.2 IC9.21(TS1) ; port TS2+
NetC84_2: C84.2 IC9.33(RST_SHUT) R101.1 R102.2
NetC86_2: C86.2 Q13.C R92.1 R93.1
NetD21_K: D21.K Q12.G R82.1 R84.2
NetD22_K: D22.K R84.1
NetD23_K: D23.K R86.2
NetD26_K: D26.K R89.1
NetD27_K: D27.K R90.2 R91.2
NetIC9_25: IC9.25(ALERT) R100.1
NetIC9_26: IC9.26(SCL) R97.1
NetIC9_27: IC9.27(SDA) R96.1
NetIC9_29: IC9.29(CFETOFF) ; port CFETOFF
NetIC9_30: IC9.30(DFETOFF) ; port DFETOFF
NetIC10_16: R100.2 ; port ALRT
NetIC10_17: R101.2 ; port RST/SHUT
NetQ10_D: Q10.D Q11.D
NetR65_1: R65.1 ; port VC12
NetR66_1: R66.1 ; port VC11
NetR67_1: R67.1 ; port VC10
NetR68_1: R68.1 ; port VC9
NetR69_1: R69.1 ; port VC8
NetR70_1: R70.1 ; port VC7
NetR71_1: R71.1 ; port VC6
NetR72_1: R72.1 ; port VC5
NetR73_1: R73.1 ; port VC4
NetR74_1: R74.1 ; port VC3
NetR75_1: R75.1 ; port VC2
NetR76_1: R76.1 ; port VC1
NetR83_1: R83.1 R85.2
NetR90_1: R90.1 R91.1 R92.2 R93.2

Not connected (* = marked no-connect by the designer): IC9 19(NC)* 22(TS2/WAKE) 23(TS3)* 28(HDQ)* 31(DCHG)* 32(DDSG)* 38(FUSE)* 39(PDSG)* 40(PCHG)* 44(NC)*

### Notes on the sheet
- (near R94) Reverse charge protection.
- (near IC9) Configure to 5V.

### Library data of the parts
C56-C69 = CL10B224KA8NNNC: Cap 220nF 25V 0603 X7R; Manufacturer: Samsung
C70-C72 C84 = CC0603KRX7R9BB104: Cap 100nF 50V 0603 X7R; Manufacturer: Yageo
C73 C74 = CC0603KRX7R0BB104: Cap 100nF 100V 0603 X7R; Manufacturer: YAGEO
C77 C86 = CC0805KKX7R0BB105: Cap 1uF 100V 0805 X7R; Manufacturer: Yageo
C78 = CL10B474KA8NNNC: Cap 470nF 25V 0603 X7R; Manufacturer: Samsung
C79-C81 = CL10A106MA8NRNC: Cap 10uF 25V 0603 X5R; Manufacturer: Samsung
C82 = CL10B223KB8NNNC: Cap 22nF 50V 0603 X7R; Manufacturer: Samsung
C83 = 0603B222K500NT: Cap 2n2F 50V 0603 X7R; Manufacturer: FH
D20 D21 D25 = BZT52C16: Zener 16V 500mW SOD-123; Manufacturer: TWGMC
D22-D24 D26-D29 = SS210F: Schottky 100V 2A 850mVf SMAF; Manufacturer: GOODWORK
IC9 = BQ76952PFBR: BMS IC 3~16s; Manufacturer: Texas Instruments
Q10 Q11 = HYG053N10NS1C2: Nmos 100V 95A 5.3mR PDFN5x6-8L; Manufacturer: HUAYI
Q12 = 2N7002: nMOS 60V 115mA SOT-23; Manufacturer: Jiangsu Changjing Electronics Technology Co., Ltd.
Q13 = CZT5551: NPN 160V 600mA SOT-223 1W; Manufacturer: Jiangsu
R64-R77 R96 R97 R100 = 0603WAF220JT5E: Res 22R 0603 1% 100mW 75V; Manufacturer: Uni-Royal
R79 R80 R89 R101 = 0603WAF1000T5E: Res 100R 0603 1% 100mW 75V; Manufacturer: Uni-Royal
R81 R82 R87 = 0603WAF1005T5E: Res 10M 0603 1% 100mW 75V; Manufacturer: Uni-Royal
R83 R85 = HP06W2J0512T5E: Res 5k1 1206 5% 500mW 200V; Manufacturer: Uni-Royal
R84 R94 R95 = 1206W4F1002T5E: Res 10k 1206 1% 250mW 200V; Manufacturer: Uni-Royal
R86 = 0603WAF5101T5E: Res 5k1 0603 1% 100mW 75V; Manufacturer: Uni-Royal
R88 R102 = 0603WAF1002T5E: Res 10k 0603 1% 100mW 75V; Manufacturer: Uni-Royal
R90-R93 = FRC1210J821 TS: Res 820R 1210 5% 500mW 200V; Manufacturer: FOJAN

## Sheet BQ34Z100 FUEL GAUGE.SchDoc
size A3; SheetNumber: 13; SheetTotal: 14
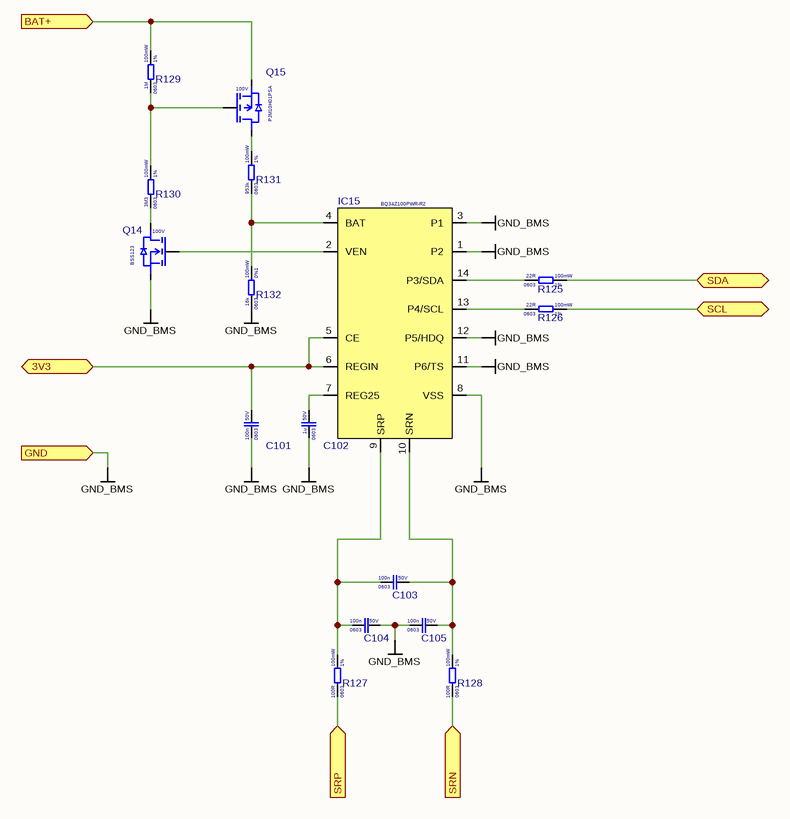
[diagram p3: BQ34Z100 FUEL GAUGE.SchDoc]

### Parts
C101  Voltage Rating: 50V  Case Code (Imperial): 0603  Capacitance: 100n  [CAP 0603]  (hidden comment: CC0603KRX7R9BB104)
C102  Voltage Rating: 50V  Case Code (Imperial): 0603  Capacitance: 1u  [CAP 0603]  (hidden comment: CL10A105KB8NNNC)
C103  Voltage Rating: 50V  Case Code (Imperial): 0603  Capacitance: 100n  [CAP 0603]  (hidden comment: CC0603KRX7R9BB104)
C104  Voltage Rating: 50V  Case Code (Imperial): 0603  Capacitance: 100n  [CAP 0603]  (hidden comment: CC0603KRX7R9BB104)
C105  Voltage Rating: 50V  Case Code (Imperial): 0603  Capacitance: 100n  [CAP 0603]  (hidden comment: CC0603KRX7R9BB104)
IC15  BQ34Z100PWR-R2  [TSSOP-14]
Q14  Voltage: 100V  [SOT-23 GSD]  (hidden comment: BSS123)
Q15  Voltage: 100V  [SOT-23 GSD]  (hidden comment: PJM10H01PSA)
R125  Resistance Tolerance: 1%  Resistance: 22R  Power Rating: 100mW  Case Code (Imperial): 0603  [RES_0603]  (hidden comment: 0603WAF220JT5E)
R126  Resistance Tolerance: 1%  Resistance: 22R  Power Rating: 100mW  Case Code (Imperial): 0603  [RES_0603]  (hidden comment: 0603WAF220JT5E)
R127  Resistance Tolerance: 1%  Resistance: 100R  Power Rating: 100mW  Case Code (Imperial): 0603  [RES_0603]  (hidden comment: 0603WAF1000T5E)
R128  Resistance Tolerance: 1%  Resistance: 100R  Power Rating: 100mW  Case Code (Imperial): 0603  [RES_0603]  (hidden comment: 0603WAF1000T5E)
R129  Resistance Tolerance: 1%  Resistance: 1M  Power Rating: 100mW  Case Code (Imperial): 0603  [RES_0603]  (hidden comment: 0603WAF1004T5E)
R130  Resistance Tolerance: 1%  Resistance: 3M3  Power Rating: 100mW  Case Code (Imperial): 0603  [RES_0603]  (hidden comment: 0603WAF3304T5E)
R131  Resistance Tolerance: 1%  Resistance: 953k  Power Rating: 100mW  Case Code (Imperial): 0603  [RES_0603]  (hidden comment: AC0603FR-07953KL)
R132  Resistance Tolerance: 0%1  Resistance: 16k  Power Rating: 100mW  Case Code (Imperial): 0603  [RES_0603]  (hidden comment: RT0603BRD0716KL)

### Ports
3V3 (bidir, see BMS[4C], 5V to 3V3 LDO[5B]), BAT+ (in, see BMS[4D], BAT+ to 5V1 STEP-DOWN[3B], BMS[1A], BQ76952 BMS[1A]), GND (in, see BMS[4D], 5V to 3V3 LDO[3B], BAT+ to 5V1 STEP-DOWN[3C], BQ76952 BMS[1D], MCU[1C]), SCL (bidir, see BMS[4C], BMS[8C], BQ76952 BMS[7C], MCU[1B]), SDA (bidir, see BMS[4C], BMS[8C], BQ76952 BMS[7C], MCU[1B]), SRN (in, see BMS[4D], BQ76952 BMS[5D]), SRP (in, see BMS[4D], BQ76952 BMS[5D])

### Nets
GND_BMS: C101.1 C102.1 C104.2 C105.1 IC15.1(P2) IC15.3(P1) IC15.8(VSS) IC15.11(P6/TS) IC15.12(P5/HDQ) Q14.S R127.1 R132.1 ; port SRP, port GND
GND_CHG: R128.1 ; port SRN
VDD: C101.2 IC15.5(CE) IC15.6(REGIN) ; port 3V3
BAT+: Q15.S R129.2 ; port BAT+
SCLt: R126.2 ; port SCL
SDAt: R125.2 ; port SDA
NetC102_2: C102.2 IC15.7(REG25)
NetC103_1: C103.1 C104.1 IC15.9(SRP) R127.2
NetC103_2: C103.2 C105.2 IC15.10(SRN) R128.2
NetIC15_2: IC15.2(VEN) Q14.G
NetIC15_4: IC15.4(BAT) R131.1 R132.2
NetIC15_13: IC15.13(P4/SCL) R126.1
NetIC15_14: IC15.14(P3/SDA) R125.1
NetQ14_D: Q14.D R130.1
NetQ15_D: Q15.D R131.2
NetQ15_G: Q15.G R129.1 R130.2

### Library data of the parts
C101 C103-C105 = CC0603KRX7R9BB104: as C70 on sheet BQ76952 BMS
C102 = CL10A105KB8NNNC: Cap 1uF 50V 0603 X5R; Manufacturer: Samsung
IC15 = BQ34Z100PWR-R2: Fuel gauge; Manufacturer: Texas Instruments
Q14 = BSS123: Nmos 100V 170mA SOT-23; Manufacturer: hongjiacheng
Q15 = PJM10H01PSA: Pmos 100V 1A 650mR SOT-23; Manufacturer: PJSEMI
R125 R126 = 0603WAF220JT5E: as R64 on sheet BQ76952 BMS
R127 R128 = 0603WAF1000T5E: as R79 on sheet BQ76952 BMS
R129 = 0603WAF1004T5E: Res 1M 0603 1% 100mW 75V; Manufacturer: Uni-Royal
R130 = 0603WAF3304T5E: Res 3M3 0603 1% 100mW 75V; Manufacturer: Uni-Royal
R131 = AC0603FR-07953KL: Res 953k 0603 1% 100mW 75V; Manufacturer: YAGEO
R132 = RT0603BRD0716KL: Res 16k 0603 0.1% 100mW 75V 25ppm; Manufacturer: YAGEO

## Sheet MCU.SchDoc
size A3; SheetNumber: 10; SheetTotal: 13
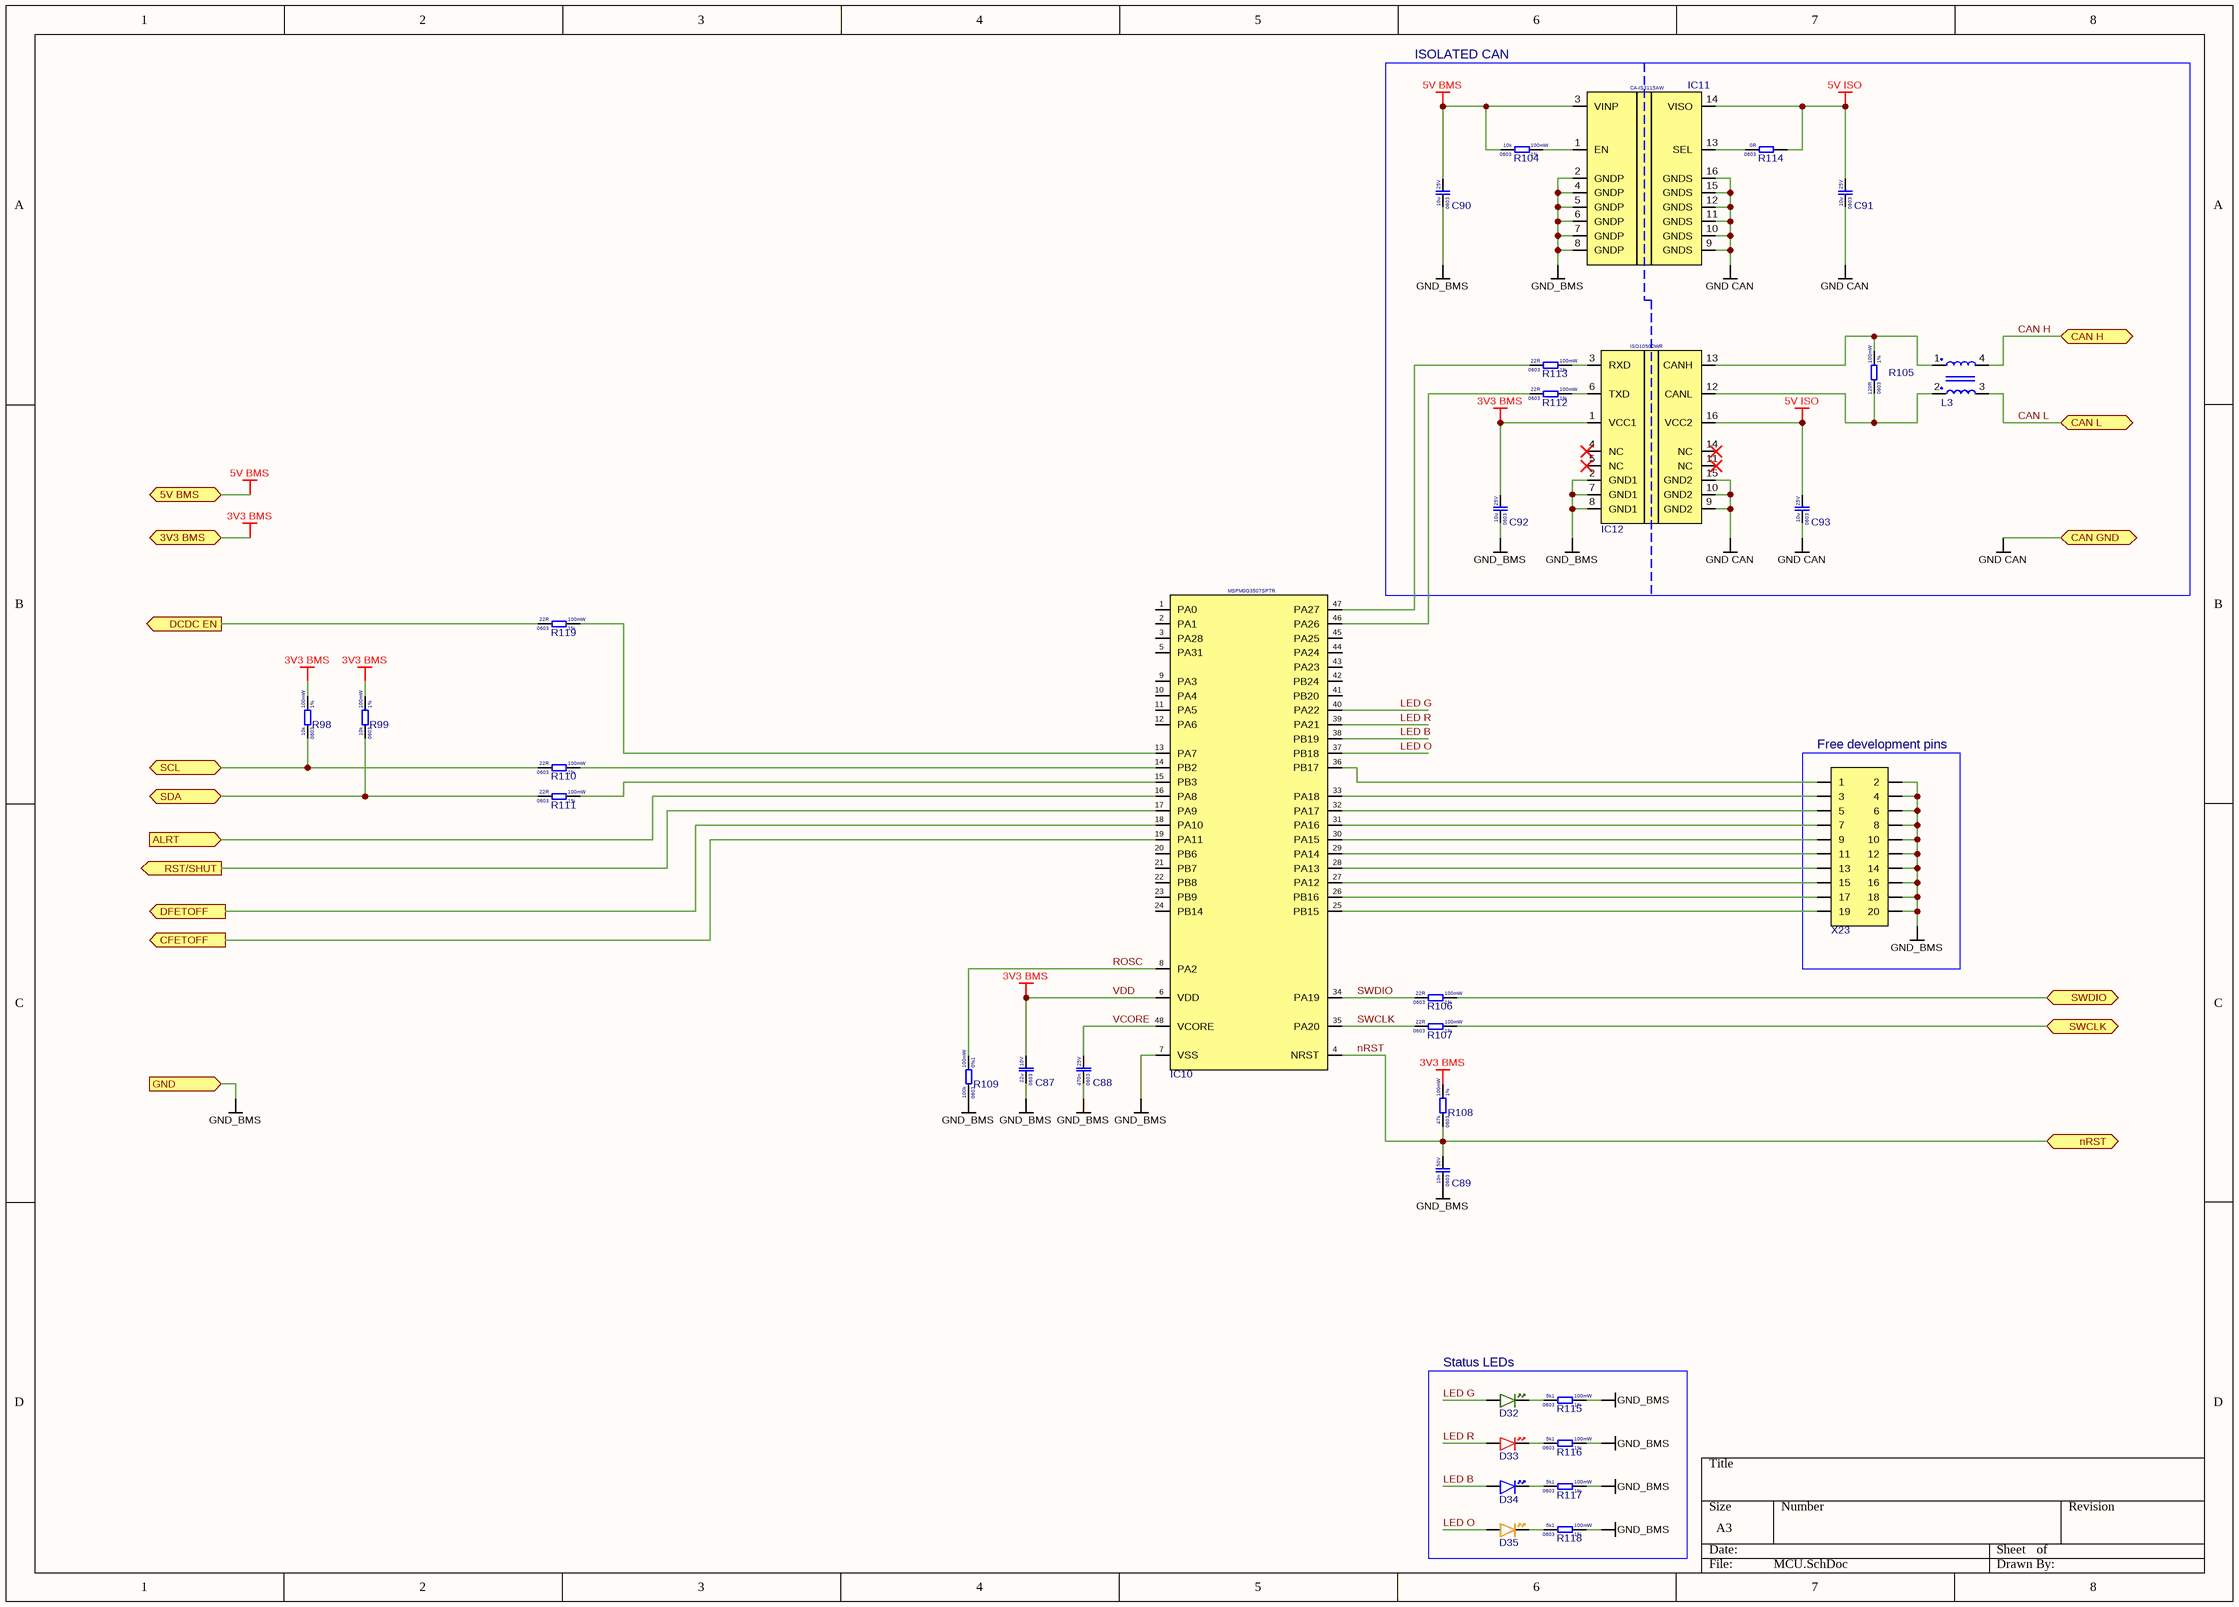
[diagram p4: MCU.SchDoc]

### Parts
C87  Voltage Rating: 10V  Case Code (Imperial): 0603  Capacitance: 22u  [CAP 0603]  (hidden comment: CGA0603X5R226M100JT)
C88  Voltage Rating: 25V  Case Code (Imperial): 0603  Capacitance: 470n  [CAP 0603]  (hidden comment: CL10B474KA8NNNC)
C89  Voltage Rating: 50V  Case Code (Imperial): 0603  Capacitance: 10n  [CAP 0603]  (hidden comment: 0603B103K500NT)
C90  Voltage Rating: 25V  Case Code (Imperial): 0603  Capacitance: 10u  [CAP 0603]  (hidden comment: CL10A106MA8NRNC)
C91  Voltage Rating: 25V  Case Code (Imperial): 0603  Capacitance: 10u  [CAP 0603]  (hidden comment: CL10A106MA8NRNC)
C92  Voltage Rating: 25V  Case Code (Imperial): 0603  Capacitance: 10u  [CAP 0603]  (hidden comment: CL10A106MA8NRNC)
C93  Voltage Rating: 25V  Case Code (Imperial): 0603  Capacitance: 10u  [CAP 0603]  (hidden comment: CL10A106MA8NRNC)
D32  PSC-1608U52GC-G4  [DIODE_0603_GREEN]  (value not drawn)
D33  XL-1608SURC-06  [DIODE_0603_RED]  (value not drawn)
D34  XL-1608UBC-04  [DIODE_0603]  (value not drawn)
D35  XL-1608UOC-06  [DIODE_0603_ORANGE]  (value not drawn)
IC10  MSPM0G3507SPTR  [LQFP-48]
IC11  CA-IS3115AW  [SOIC-16-WB]
IC12  ISO1050DWR  [SOIC-16-WB]
L3  ACM2012-900-2P-T002  [ACM2012-900-2P-T002]  (value not drawn)
R98  Resistance Tolerance: 1%  Resistance: 10k  Power Rating: 100mW  Case Code (Imperial): 0603  [RES_0603]  (hidden comment: 0603WAF1002T5E)
R99  Resistance Tolerance: 1%  Resistance: 10k  Power Rating: 100mW  Case Code (Imperial): 0603  [RES_0603]  (hidden comment: 0603WAF1002T5E)
R104  Resistance Tolerance: 1%  Resistance: 10k  Power Rating: 100mW  Case Code (Imperial): 0603  [RES_0603]  (hidden comment: 0603WAF1002T5E)
R105  Resistance Tolerance: 1%  Resistance: 120R  Power Rating: 100mW  Case Code (Imperial): 0603  [RES_0603]  (hidden comment: 0603WAF1200T5E)
R106  Resistance Tolerance: 1%  Resistance: 22R  Power Rating: 100mW  Case Code (Imperial): 0603  [RES_0603]  (hidden comment: 0603WAF220JT5E)
R107  Resistance Tolerance: 1%  Resistance: 22R  Power Rating: 100mW  Case Code (Imperial): 0603  [RES_0603]  (hidden comment: 0603WAF220JT5E)
R108  Resistance Tolerance: 1%  Resistance: 47k  Power Rating: 100mW  Case Code (Imperial): 0603  [RES_0603]  (hidden comment: 0603WAF4702T5E)
R109  Resistance Tolerance: 0%1  Resistance: 100k  Power Rating: 100mW  Case Code (Imperial): 0603  [RES_0603]  (hidden comment: RT0603BRD07100KL)
R110  Resistance Tolerance: 1%  Resistance: 22R  Power Rating: 100mW  Case Code (Imperial): 0603  [RES_0603]  (hidden comment: 0603WAF220JT5E)
R111  Resistance Tolerance: 1%  Resistance: 22R  Power Rating: 100mW  Case Code (Imperial): 0603  [RES_0603]  (hidden comment: 0603WAF220JT5E)
R112  Resistance Tolerance: 1%  Resistance: 22R  Power Rating: 100mW  Case Code (Imperial): 0603  [RES_0603]  (hidden comment: 0603WAF220JT5E)
R113  Resistance Tolerance: 1%  Resistance: 22R  Power Rating: 100mW  Case Code (Imperial): 0603  [RES_0603]  (hidden comment: 0603WAF220JT5E)
R114  Resistance: 0R  Case Code (Imperial): 0603  [RES_0603]  (hidden comment: 0603WAF0000T5E)
R115  Resistance Tolerance: 1%  Resistance: 5k1  Power Rating: 100mW  Case Code (Imperial): 0603  [RES_0603]  (hidden comment: 0603WAF5101T5E)
R116  Resistance Tolerance: 1%  Resistance: 5k1  Power Rating: 100mW  Case Code (Imperial): 0603  [RES_0603]  (hidden comment: 0603WAF5101T5E)
R117  Resistance Tolerance: 1%  Resistance: 5k1  Power Rating: 100mW  Case Code (Imperial): 0603  [RES_0603]  (hidden comment: 0603WAF5101T5E)
R118  Resistance Tolerance: 1%  Resistance: 5k1  Power Rating: 100mW  Case Code (Imperial): 0603  [RES_0603]  (hidden comment: 0603WAF5101T5E)
R119  Resistance Tolerance: 1%  Resistance: 22R  Power Rating: 100mW  Case Code (Imperial): 0603  [RES_0603]  (hidden comment: 0603WAF220JT5E)
X23  PZ254V-12-20P  [Pin header 2x10 2.54mm THT Vertical]  (value not drawn)

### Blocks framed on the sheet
ISOLATED CAN: C90-C93 IC11 IC12 L3 R104 R105 R112-R114
Free development pins: X23
Status LEDs: D32-D35 R115-R118

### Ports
3V3 BMS (bidir, see BMS[4B]), 5V BMS (bidir, see BMS[4B]), ALRT (in, see BMS[4B], BQ76952 BMS[7C]), CAN GND (bidir, see BMS[4B], BMS[8B]), CAN H (bidir, see BMS[4B], BMS[8B], ESD system side[2B]), CAN L (bidir, see BMS[4B], BMS[8B], ESD system side[2B]), CFETOFF (out, see BMS[4B], BQ76952 BMS[7C]), DCDC EN (out, see BMS[4B]), DFETOFF (out, see BMS[4B], BQ76952 BMS[7C]), GND (in, see BMS[4C], 5V to 3V3 LDO[3B], BAT+ to 5V1 STEP-DOWN[3C], BQ76952 BMS[1D]), nRST (bidir, see BMS[4B], BMS[8B]), RST/SHUT (out, see BMS[4B], BQ76952 BMS[7C]), SCL (bidir, see BMS[4C], BMS[8C], BQ76952 BMS[7C]), SDA (bidir, see BMS[4C], BMS[8C], BQ76952 BMS[7C]), SWCLK (bidir, see BMS[4B], BMS[8B]), SWDIO (bidir, see BMS[4B], BMS[8B])

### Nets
5V BMS: C90.2 IC11.3(VINP) R104.1 ; port 5V BMS
5V ISO: C91.2 C93.2 IC11.14(VISO) IC12.16(VCC2) R114.2
GND CAN: C91.1 C93.1 IC11.9(GNDS) IC11.10(GNDS) IC11.11(GNDS) IC11.12(GNDS) IC11.15(GNDS) IC11.16(GNDS) IC12.9(GND2) IC12.10(GND2) IC12.15(GND2) ; port CAN GND
GND_BMS: C87.1 C88.1 C89.1 C90.1 C92.1 IC10.7(VSS) IC11.2(GNDP) IC11.4(GNDP) IC11.5(GNDP) IC11.6(GNDP) IC11.7(GNDP) IC11.8(GNDP) IC12.2(GND1) IC12.7(GND1) IC12.8(GND1) R109.1 R115.2 R116.2 R117.2 R118.2 X23.2 X23.4 X23.6 X23.8 X23.10 X23.12 X23.14 X23.16 X23.18 X23.20 ; port GND
VDD: C87.2 C92.2 IC10.6(VDD) IC12.1(VCC1) R98.2 R99.2 R108.2 ; port 3V3 BMS  [also labelled 3V3 BMS]
CAN H: L3.4 ; port CAN H
CAN L: L3.3 ; port CAN L
LED B: D34.A IC10.38(PB19)
LED G: D32.A IC10.40(PA22)
LED O: D35.A IC10.37(PB18)
LED R: D33.A IC10.39(PA21)
nRST: C89.2 IC10.4(NRST) R108.1 ; port nRST
ROSC: IC10.8(PA2) R109.2
SCLt: R98.1 R110.1 ; port SCL
SDAt: R99.1 R111.1 ; port SDA
SWCLK: IC10.35(PA20) R107.1
SWDIO: IC10.34(PA19) R106.1
VCORE: C88.2 IC10.48(VCORE)
NetD32_K: D32.K R115.1
NetD33_K: D33.K R116.1
NetD34_K: D34.K R117.1
NetD35_K: D35.K R118.1
NetD49_K: R106.2 ; port SWDIO
NetD50_K: R107.2 ; port SWCLK
NetIC9_29: IC10.19(PA11) ; port CFETOFF
NetIC9_30: IC10.18(PA10) ; port DFETOFF
NetIC10_13: IC10.13(PA7) R119.2
NetIC10_14: IC10.14(PB2) R110.2
NetIC10_15: IC10.15(PB3) R111.2
NetIC10_16: IC10.16(PA8) ; port ALRT
NetIC10_17: IC10.17(PA9) ; port RST/SHUT
NetIC10_25: IC10.25(PB15) X23.19
NetIC10_26: IC10.26(PB16) X23.17
NetIC10_27: IC10.27(PA12) X23.15
NetIC10_28: IC10.28(PA13) X23.13
NetIC10_29: IC10.29(PA14) X23.11
NetIC10_30: IC10.30(PA15) X23.9
NetIC10_31: IC10.31(PA16) X23.7
NetIC10_32: IC10.32(PA17) X23.5
NetIC10_33: IC10.33(PA18) X23.3
NetIC10_36: IC10.36(PB17) X23.1
NetIC10_46: IC10.46(PA26) R112.1
NetIC10_47: IC10.47(PA27) R113.1
NetIC11_1: IC11.1(EN) R104.2
NetIC11_13: IC11.13(SEL) R114.1
NetIC12_3: IC12.3(RXD) R113.2
NetIC12_6: IC12.6(TXD) R112.2
NetIC12_12: IC12.12(CANL) L3.2 R105.1
NetIC12_13: IC12.13(CANH) L3.1 R105.2
NetIC13_3: R119.1 ; port DCDC EN

Not connected (* = marked no-connect by the designer): IC10 1(PA0) 2(PA1) 3(PA28) 5(PA31) 9(PA3) 10(PA4) 11(PA5) 12(PA6) 20(PB6) 21(PB7) 22(PB8) 23(PB9) 24(PB14) 41(PB20) 42(PB24) 43(PA23) 44(PA24) 45(PA25); IC12 4(NC)* 5(NC)* 11(NC)* 14(NC)*

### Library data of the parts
C87 = CGA0603X5R226M100JT: Cap 22uF 10V 0603 X5R; Manufacturer: HRE
C88 = CL10B474KA8NNNC: as C78 on sheet BQ76952 BMS
C89 = 0603B103K500NT: Cap 10nF 50V 0603 X7R; Manufacturer: FH
C90-C93 = CL10A106MA8NRNC: as C79 on sheet BQ76952 BMS
D32 = PSC-1608U52GC-G4: LED Green 0603 20mA; Manufacturer: HONGLITRONIC
D33 = XL-1608SURC-06: LED Red 0603 25mA; Manufacturer: Xinglight
D34 = XL-1608UBC-04: LED Blue 0603 25mA; Manufacturer: Xinglight
D35 = XL-1608UOC-06: LED Orange 0603 20mA; Manufacturer: XINGLIGHT
IC10 = MSPM0G3507SPTR: MCU MSPM0G3507SPTR LQFP-48; Manufacturer: Texas Instruments
IC11 = CA-IS3115AW: DCDC Module Isolated 5Vin 5Vout 1.5W SOIC-16-WB; Manufacturer: Chipanalog
IC12 = ISO1050DWR: CAN ISO transciever SOIC-16-WB; Manufacturer: Texas Instruments
L3 = ACM2012-900-2P-T002: CMC 90R@100MHz 190mR 400mA 50V; Manufacturer: TDK
R98 R99 R104 = 0603WAF1002T5E: as R88 on sheet BQ76952 BMS
R105 = 0603WAF1200T5E: Res 120R 0603 1% 100mW 75V; Manufacturer: Uni-Royal; Manufacturer Part Number: 0603WAF5101T5E
R106 R107 R110-R113 R119 = 0603WAF220JT5E: as R64 on sheet BQ76952 BMS
R108 = 0603WAF4702T5E: Res 47k 0603 1% 100mW 75V; Manufacturer: Uni-Royal
R109 = RT0603BRD07100KL: Res 100k 0603 0.1% 100mW 75V 25ppm; Manufacturer: YAGEO
R114 = 0603WAF0000T5E: Res 0R 0603 1% 100mW 75V; Manufacturer: UNI-ROYAL
R115-R118 = 0603WAF5101T5E: as R86 on sheet BQ76952 BMS
X23 = PZ254V-12-20P: Pin header 2x10 2.54mm THT Vertical; Manufacturer: XFCN

## Sheet BAT+ to 5V1 STEP-DOWN.SchDoc
size A3; SheetNumber: 11; SheetTotal: 15
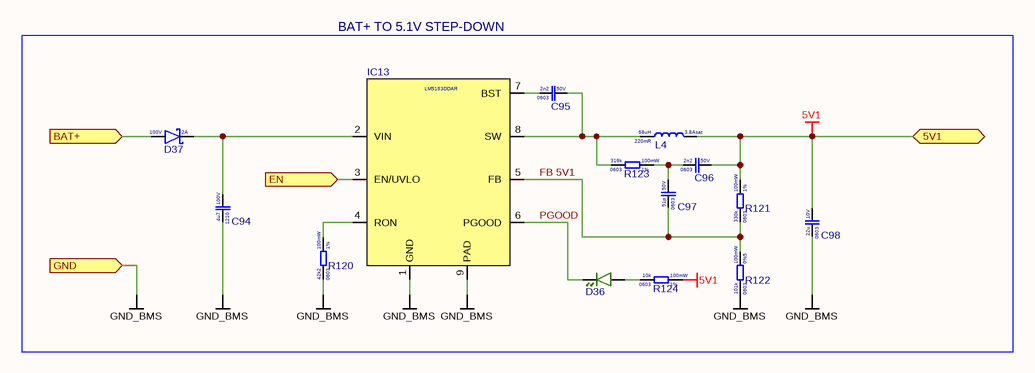
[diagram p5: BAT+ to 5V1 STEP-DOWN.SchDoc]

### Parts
C94  Voltage Rating: 100V  Case Code (Imperial): 1210  Capacitance: 4u7  [CAP_1210]  (hidden comment: HMK325C7475KN-TE)
C95  Voltage Rating: 50V  Case Code (Imperial): 0603  Capacitance: 2n2  [CAP 0603]  (hidden comment: 0603B222K500NT)
C96  Voltage Rating: 50V  Case Code (Imperial): 0603  Capacitance: 2n2  [CAP 0603]  (hidden comment: 0603B222K500NT)
C97  Voltage Rating: 50V  Case Code (Imperial): 0603  Capacitance: 51p  [CAP 0603]  (hidden comment: CC0603JRNPO9BN510)
C98  Voltage Rating: 10V  Case Code (Imperial): 0603  Capacitance: 22u  [CAP 0603]  (hidden comment: CGA0603X5R226M100JT)
D36  PSC-1608U52GC-G4  [DIODE_0603_GREEN]  (value not drawn)
D37  Forward Current: 2A  Reverse Voltage: 100V  [SMAF]  (hidden comment: SS210F)
IC13  LM5163DDAR  [ESOP-8]
L4  Resistance: 220mR  Saturation current: 3.8Asat  Inductance: 68uH  [IND 11.5x10mm]  (hidden comment: SMMS1040-680MT)
R120  Resistance Tolerance: 1%  Resistance: 42k2  Power Rating: 100mW  Case Code (Imperial): 0603  [RES_0603]  (hidden comment: 0603WAF4222T5E)
R121  Resistance Tolerance: 1%  Resistance: 330k  Power Rating: 100mW  Case Code (Imperial): 0603  [RES_0603]  (hidden comment: 0603WAF3303T5E)
R122  Resistance Tolerance: 0%5  Resistance: 101k  Power Rating: 100mW  Case Code (Imperial): 0603  [RES_0603]  (hidden comment: RT0603DRE07101KL)
R123  Resistance Tolerance: 1%  Resistance: 316k  Power Rating: 100mW  Case Code (Imperial): 0603  [RES_0603]  (hidden comment: 0603WAF3163T5E)
R124  Resistance Tolerance: 1%  Resistance: 10k  Power Rating: 100mW  Case Code (Imperial): 0603  [RES_0603]  (hidden comment: 0603WAF1002T5E)

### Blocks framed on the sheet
BAT+ TO 5.1V STEP-DOWN: C94-C98 D36 D37 IC13 L4 R120-R124

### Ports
5V1 (bidir, see BMS[4B]), BAT+ (in, see BMS[4B], BMS[1A], BQ34Z100 FUEL GAUGE[3A], BQ76952 BMS[1A], ESD battery side[5A]), EN (in, see BMS[4B]), GND (in, see BMS[4B], 5V to 3V3 LDO[3B], BQ34Z100 FUEL GAUGE[3C], BQ76952 BMS[1D], MCU[1C])

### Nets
5V1: C96.2 C98.2 L4.2 R121.2 R124.2 ; port 5V1  [project net 5V BMS]
GND_BMS: C94.1 C98.1 IC13.1(GND) IC13.9(PAD) R120.1 R122.1 ; port GND
BAT+: D37.A ; port BAT+
FB 5V1: C97.1 IC13.5(FB) R121.1 R122.2
PGOOD: D36.K IC13.6(PGOOD)
NetC94_2: C94.2 D37.K IC13.2(VIN)
NetC95_1: C95.1 IC13.7(BST)
NetC95_2: C95.2 IC13.8(SW) L4.1 R123.1
NetC96_1: C96.1 C97.2 R123.2
NetD36_A: D36.A R124.1
NetIC13_3: IC13.3(EN/UVLO) ; port EN
NetIC13_4: IC13.4(RON) R120.2

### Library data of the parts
C94 = HMK325C7475KN-TE: Cap 4.7uF 100V 1210 X7R; Manufacturer: Taiyo Yuden
C95 C96 = 0603B222K500NT: Cap 2n2F 50V 0603 X7R; Manufacturer: FH
C97 = CC0603JRNPO9BN510: Cap 51pF 50V 0603 NP0; Manufacturer: Yageo
C98 = CGA0603X5R226M100JT: Cap 22uF 10V 0603 X5R; Manufacturer: HRE
D36 = PSC-1608U52GC-G4: as D32 on sheet MCU
D37 = SS210F: as D22 on sheet BQ76952 BMS
IC13 = LM5163DDAR: DCDC Step-down Converter 9~100Vin 0.5Aout; Manufacturer: Texas Instruments
L4 = SMMS1040-680MT: Inductor 68uH 3.8A 220mR SMD 11.5x10mm; Manufacturer: SXN
R120 = 0603WAF4222T5E: Res 42k2 0603 1% 100mW 75V; Manufacturer: Uni-Royal
R121 = 0603WAF3303T5E: Res 330k 0603 1% 100mW 75V; Manufacturer: Uni-Royal
R122 = RT0603DRE07101KL: Res 101k 0603 0.5% 100mW 75V; Manufacturer: YAGEO
R123 = 0603WAF3163T5E: Res 316k 0603 1% 100mW 75V; Manufacturer: Uni-Royal
R124 = 0603WAF1002T5E: as R88 on sheet BQ76952 BMS

## Sheet 5V to 3V3 LDO.SchDoc
size A3; SheetNumber: 12; SheetTotal: 13
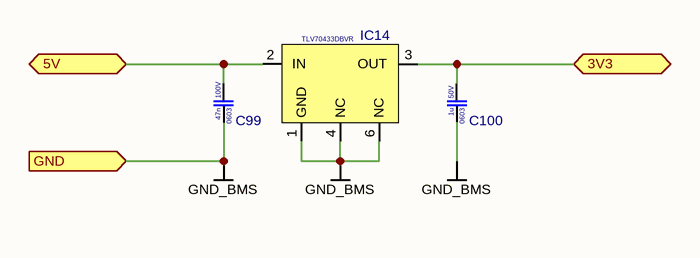
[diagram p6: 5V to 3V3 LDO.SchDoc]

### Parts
C99  Voltage Rating: 100V  Case Code (Imperial): 0603  Capacitance: 47n  [CAP 0603]  (hidden comment: CC0603KRX7R0BB473)
C100  Voltage Rating: 50V  Case Code (Imperial): 0603  Capacitance: 1u  [CAP 0603]  (hidden comment: CL10A105KB8NNNC)
IC14  TLV70433DBVR  [SOT-23-5]

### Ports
3V3 (bidir, see BMS[6B]), 5V (bidir, see BMS[5B]), GND (in, see BMS[5B], BAT+ to 5V1 STEP-DOWN[3C], BQ76952 BMS[1D], MCU[1C])

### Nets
5V BMS: C99.2 IC14.2(IN) ; port 5V
GND_BMS: C99.1 C100.1 IC14.1(GND) IC14.4(NC) IC14.6(NC) ; port GND
VDD: C100.2 IC14.3(OUT) ; port 3V3

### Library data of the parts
C99 = CC0603KRX7R0BB473: Cap 47nF 100V 0603 X7R; Manufacturer: Yageo
C100 = CL10A105KB8NNNC: as C102 on sheet BQ34Z100 FUEL GAUGE
IC14 = TLV70433DBVR: LDO 24Vin 3.3Vout 150mA SOT-23-5; Manufacturer: Texas Instruments

## Sheet CHARGER.SchDoc
size A3; SheetNumber: 2; SheetTotal: 15
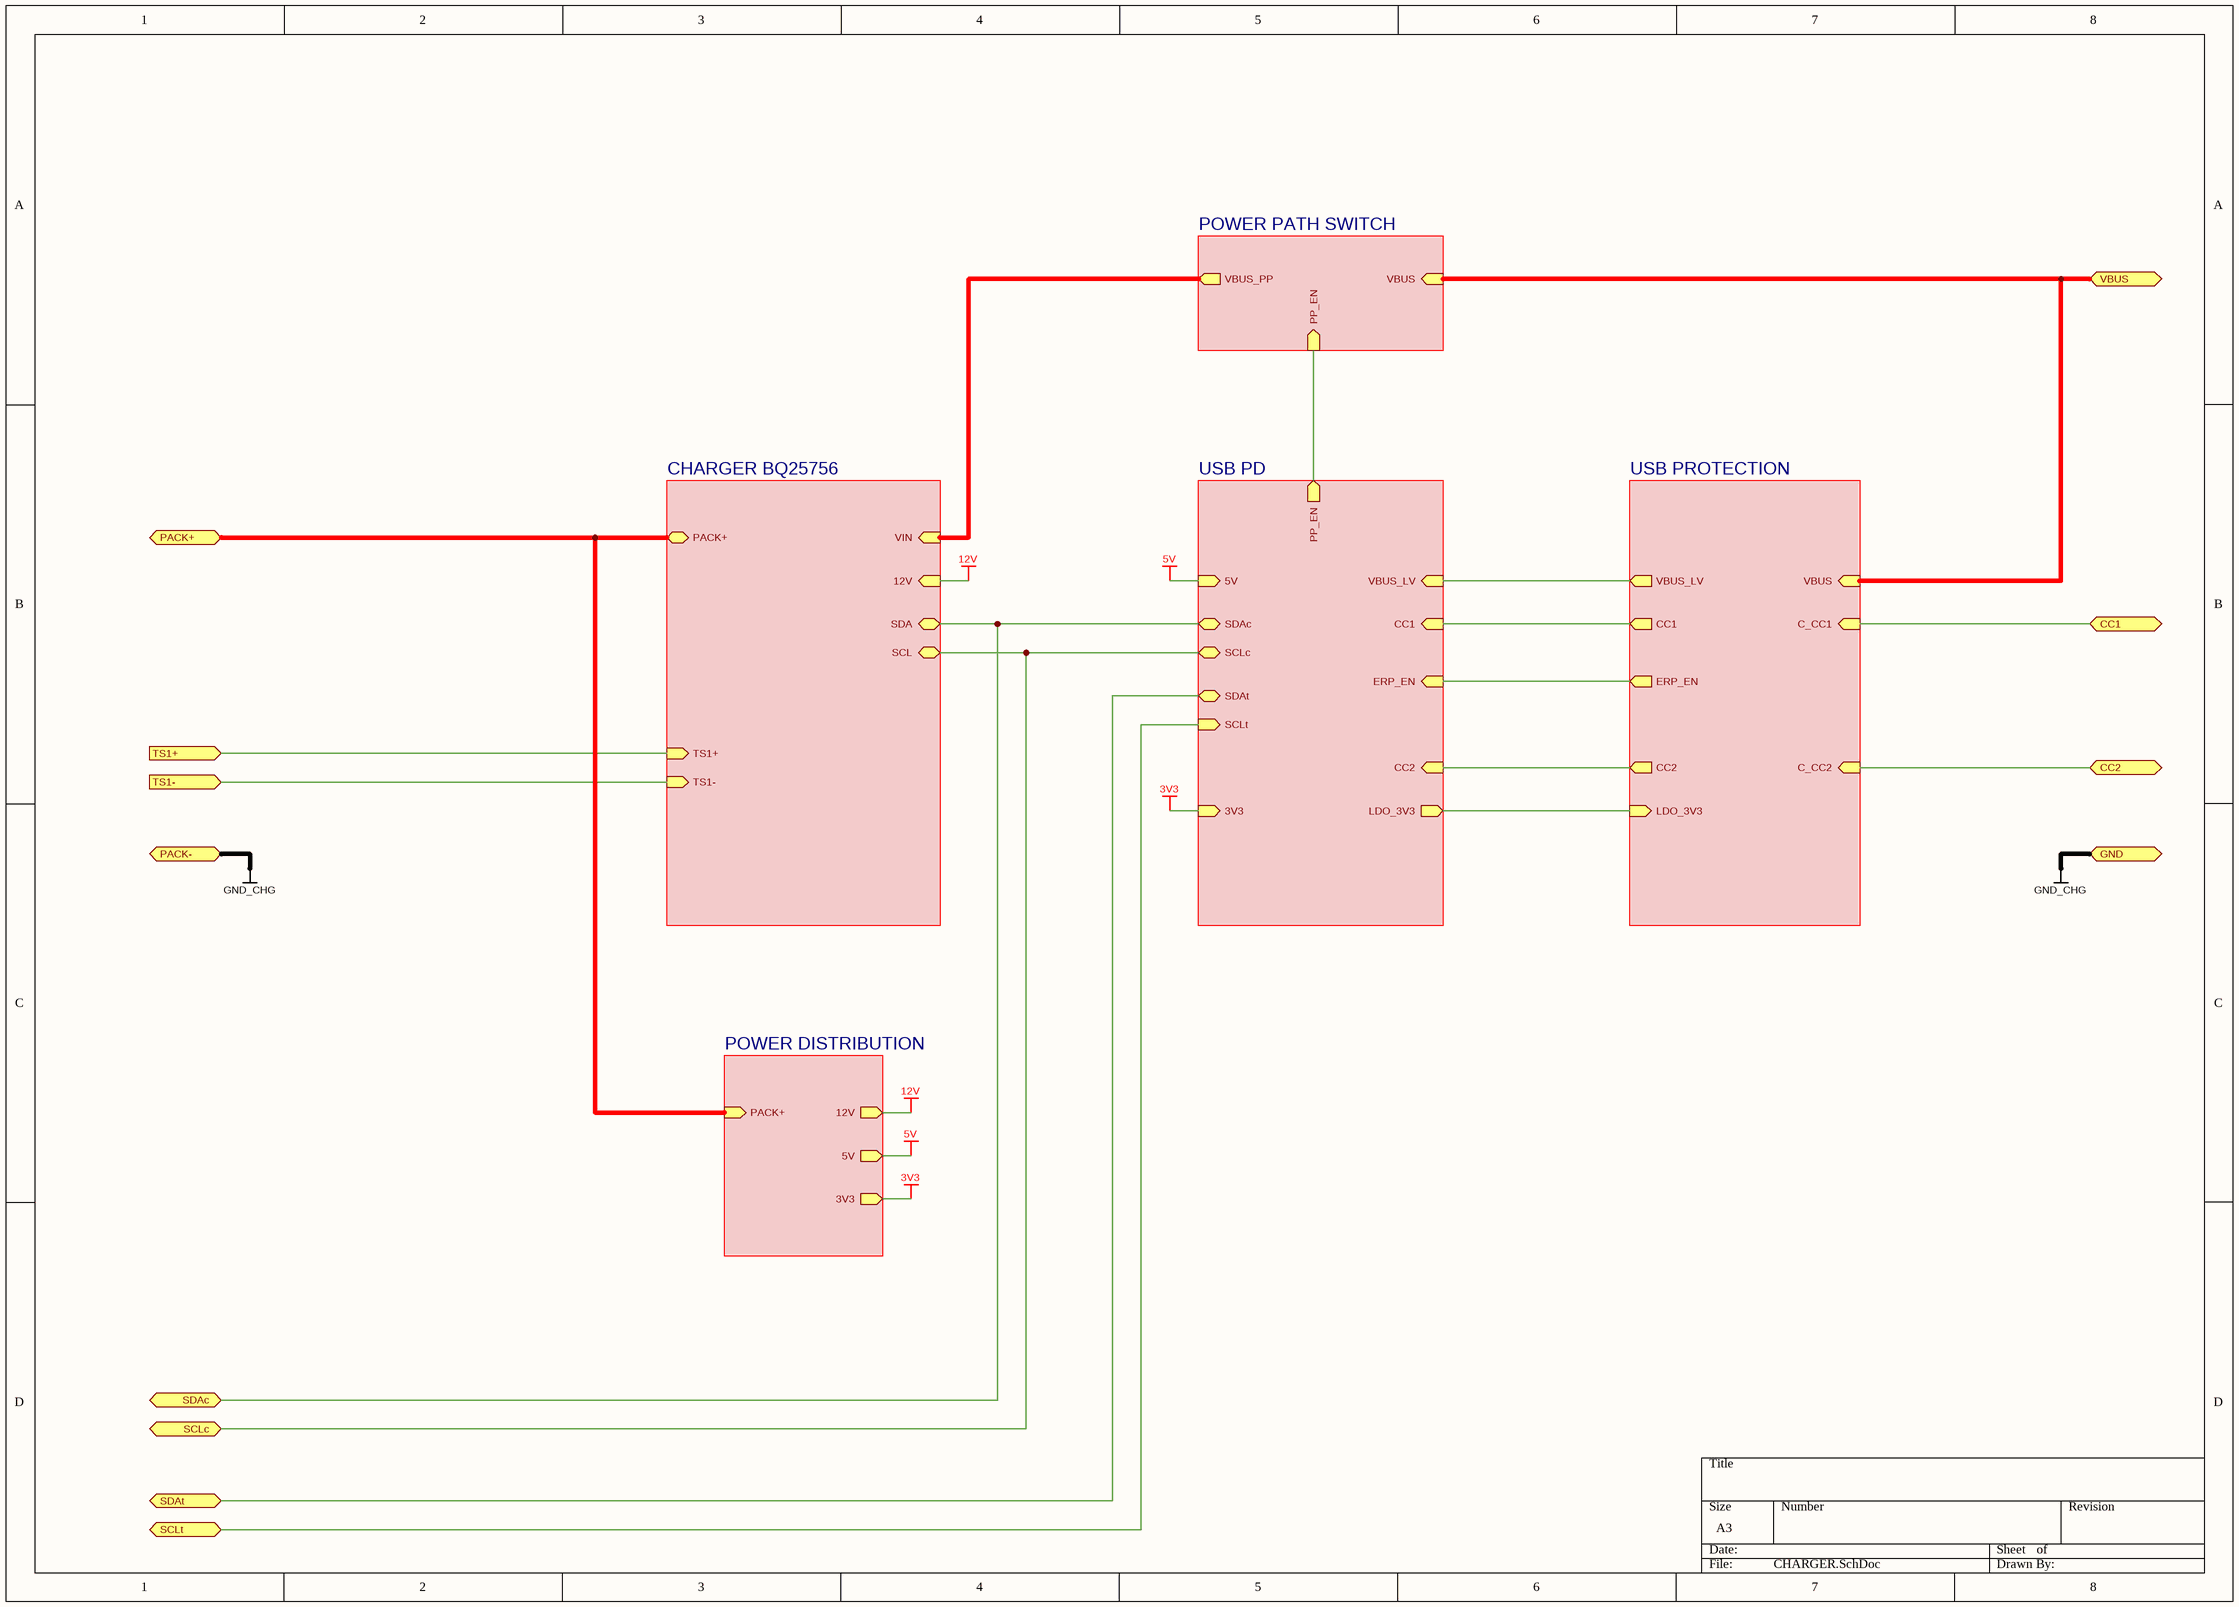
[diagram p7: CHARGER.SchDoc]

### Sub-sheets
CHARGER BQ25756 = Charger BQ25756.SchDoc: PACK+ (bidir), VIN (in), SDA (bidir), SCL (bidir), 12V (in), TS1+ (in), TS1- (in)
POWER DISTRIBUTION = Power distribution.SchDoc: PACK+ (in), 12V (out), 5V (out), 3V3 (out)
POWER PATH SWITCH = Power path switch.SchDoc: VBUS (in), VBUS_PP (out), PP_EN (in)
USB PD = USB PD.SchDoc: VBUS_LV (in), ERP_EN (in), CC1 (in), LDO_3V3 (out), SDAc (bidir), SCLc (bidir), 5V (in), 3V3 (in), CC2 (in), PP_EN (out), SDAt (bidir), SCLt (in)
USB PROTECTION = USB protection.SchDoc: VBUS (in), C_CC1 (in), C_CC2 (in), VBUS_LV (out), ERP_EN (out), CC1 (out), LDO_3V3 (in), CC2 (out)

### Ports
CC1 (bidir, see Arhitecture[6B], ESD system side[3C]), CC2 (bidir, see Arhitecture[6C], ESD system side[3C]), GND (bidir, see Arhitecture[6C], ESD system side[3C]), PACK+ (bidir, see Arhitecture[6B], BMS[8A], BQ76952 BMS[8A], Charger BQ25756[1A], Power distribution[3A]), PACK- (bidir, see Arhitecture[6C], BMS[8D], ESD system side[3C]), SCLc (bidir, see Arhitecture[6C], USB PD[7B]), SCLt (bidir, see Arhitecture[6C], USB PD[7B]), SDAc (bidir, see Arhitecture[6C], USB PD[7B]), SDAt (bidir, see Arhitecture[6C], USB PD[7B]), TS1+ (in, see Arhitecture[6B], Charger BQ25756[2C], ESD battery side[5C]), TS1- (in, see Arhitecture[6B], Charger BQ25756[2C], ESD battery side[5C]), VBUS (bidir, see Arhitecture[6B], ESD system side[3C], Power path switch[5B], USB protection[5A])

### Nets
3V3: sheet USB PD/3V3, sheet POWER DISTRIBUTION/3V3
5V: sheet USB PD/5V, sheet POWER DISTRIBUTION/5V
12V: sheet CHARGER BQ25756/12V, sheet POWER DISTRIBUTION/12V
GND_CHG: port PACK-, port GND
LDO_3V3: sheet USB PROTECTION/LDO_3V3, sheet USB PD/LDO_3V3
C_CC1: port CC1, sheet USB PROTECTION/C_CC1
C_CC2: port CC2, sheet USB PROTECTION/C_CC2
CC1: sheet USB PROTECTION/CC1, sheet USB PD/CC1
CC2: sheet USB PROTECTION/CC2, sheet USB PD/CC2
ERP_EN: sheet USB PROTECTION/ERP_EN, sheet USB PD/ERP_EN
PACK+: port PACK+, sheet CHARGER BQ25756/PACK+, sheet POWER DISTRIBUTION/PACK+
PP_EN: sheet USB PD/PP_EN, sheet POWER PATH SWITCH/PP_EN
SCL: port SCLc, sheet USB PD/SCLc, sheet CHARGER BQ25756/SCL
SCLt: port SCLt, sheet USB PD/SCLt
SDA: port SDAc, sheet USB PD/SDAc, sheet CHARGER BQ25756/SDA
SDAt: port SDAt, sheet USB PD/SDAt
TS: port TS1+, sheet CHARGER BQ25756/TS1+
V_CHG_IN: sheet POWER PATH SWITCH/VBUS_PP, sheet CHARGER BQ25756/VIN
VBUS: port VBUS, sheet USB PROTECTION/VBUS, sheet POWER PATH SWITCH/VBUS
VBUS_LV: sheet USB PROTECTION/VBUS_LV, sheet USB PD/VBUS_LV
NetD40_A: port TS1-, sheet CHARGER BQ25756/TS1-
